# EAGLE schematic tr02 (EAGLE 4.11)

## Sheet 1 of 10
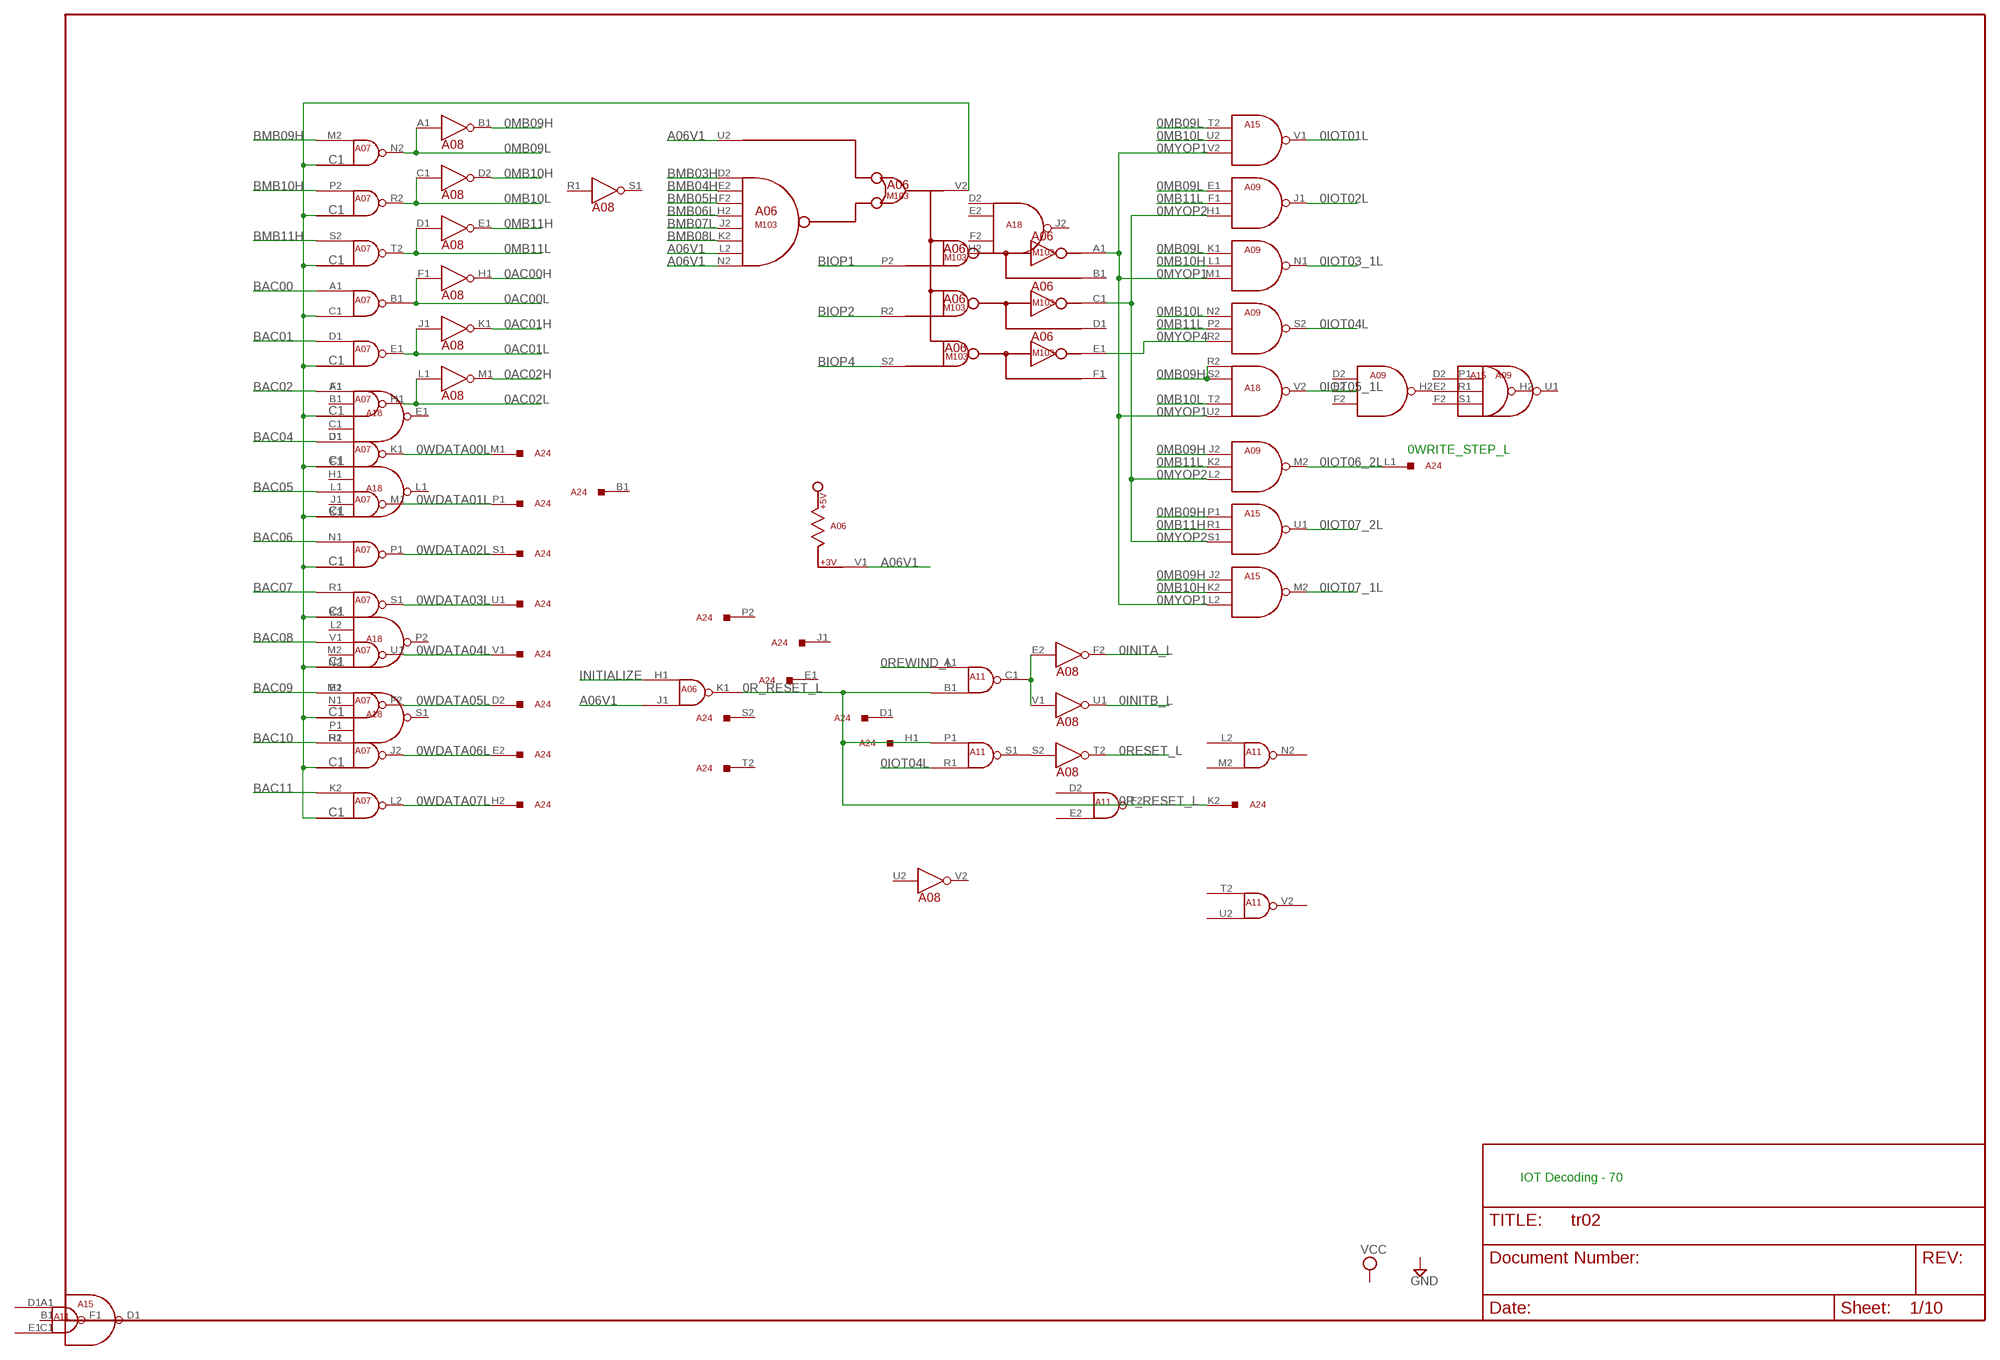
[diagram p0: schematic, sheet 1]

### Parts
A06  M103  [H807]
A07  M101  [H807]
A08  M111  [H807]
A09  M115  [H807]
A11  M113  [H807]
A15  M115  [H807]
A18  M117  [H807]
A24  G784  M916  [H807]

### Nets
0AC00H: A08.H1(4:OUT) ; also sheet 3
0AC00L: A07.B1(OUT) A08.F1(4:IN) ; also sheet 3
0AC01H: A08.K1(6:OUT) ; also sheet 3
0AC01L: A07.E1(OUT) A08.J1(6:IN) ; also sheet 3
0AC02H: A08.M1(8:OUT) ; also sheet 3
0AC02L: A07.H1(OUT) A08.L1(8:IN) ; also sheet 3
0INITA_L: A08.F2(5:OUT) ; also sheet 3
0INITB_L: A08.U1(14:OUT) ; also sheet 3
0IOT01L: A15.V1(OUT) ; also sheet 6
0IOT02L: A09.J1(OUT) ; also sheet 5
0IOT03_1L: A09.N1(OUT) ; also sheet 6
0IOT04L: A09.S2(OUT) A11.R1(IN2) ; also sheet 3
0IOT05_1L: A18.V2(OUT) ; also sheet 6
0IOT06_2L: A09.M2(OUT) A24.L1
0IOT07_1L: A15.M2(OUT) ; also sheet 6
0IOT07_2L: A15.U1(OUT) ; also sheet 5
0MB09H: A08.B1(1:OUT) A09.J2(IN1) A15.J2(IN1) A15.P1(IN1) A18.R2(IN1) A18.S2(IN2)
0MB09L: A07.N2(OUT) A08.A1(1:IN) A09.E1(IN1) A09.K1(IN1) A15.T2(IN1)
0MB10H: A08.D2(2:OUT) A09.L1(IN2) A15.K2(IN2)
0MB10L: A07.R2(OUT) A08.C1(2:IN) A09.N2(IN1) A15.U2(IN2) A18.T2(IN3)
0MB11H: A08.E1(3:OUT) A15.R1(IN2)
0MB11L: A07.T2(OUT) A08.D1(3:IN) A09.F1(IN2) A09.K2(IN2) A09.P2(IN2)
0MYOP1: A06.A1 A09.M1(IN3) A15.L2(IN3) A15.V2(IN3) A18.U2(IN4)
0MYOP2: A06.C1 A09.H1(IN3) A09.L2(IN3) A15.S1(IN3)
0MYOP4: A06.E1 A09.R2(IN3)
0R_RESET_L: A06.K1(OUT) A11.B1(IN2) A11.P1(IN1) A24.K2
0RESET_L: A08.T2(15:OUT) ; also sheet 5,6
0REWIND_L: A11.A1(IN1) ; also sheet 3
0WDATA00L: A07.K1(OUT) A24.M1
0WDATA01L: A07.M1(OUT) A24.P1
0WDATA02L: A07.P1(OUT) A24.S1
0WDATA03L: A07.S1(OUT) A24.U1
0WDATA04L: A07.U1(OUT) A24.V1
0WDATA05L: A07.F2(OUT) A24.D2
0WDATA06L: A07.J2(OUT) A24.E2
0WDATA07L: A07.L2(OUT) A24.H2
A06V1: A06.J1(IN2) A06.L2 A06.N2 A06.U2 A06.V1
BAC00: A07.A1(IN1) ; also sheet 2,10
BAC01: A07.D1(IN) ; also sheet 2,10
BAC02: A07.F1(IN) ; also sheet 2,10
BAC04: A07.J1(IN) ; also sheet 2,10
BAC05: A07.L1(IN) ; also sheet 2,10
BAC06: A07.N1(IN) ; also sheet 2,10
BAC07: A07.R1(IN) ; also sheet 2,10
BAC08: A07.V1(IN) ; also sheet 2,10
BAC09: A07.E2(IN) ; also sheet 2,10
BAC10: A07.H2(IN) ; also sheet 2,10
BAC11: A07.K2(IN) ; also sheet 2,10
BIOP1: A06.P2 ; also sheet 2,10
BIOP2: A06.R2 ; also sheet 2,10
BIOP4: A06.S2 ; also sheet 2,10
BMB03H: A06.D2 ; also sheet 2,10
BMB04H: A06.E2 ; also sheet 2,10
BMB05H: A06.F2 ; also sheet 2,10
BMB06L: A06.H2 ; also sheet 2,10
BMB07L: A06.J2 ; also sheet 2,10
BMB08L: A06.K2 ; also sheet 10
BMB09H: A07.M2(IN) ; also sheet 2,10
BMB10H: A07.P2(IN) ; also sheet 2,10
BMB11H: A07.S2(IN) ; also sheet 2,10
INITIALIZE: A06.H1(IN1) ; also sheet 2,10
N$7: A06.V2 A07.C1(IN2)
N$8: A08.S2(15:IN) A11.S1(OUT)
N$9: A08.E2(5:IN) A08.V1(14:IN) A11.C1(OUT)
Unconnected: A06.B1 A06.D1 A06.F1 A06.L1(IN1) A06.M1(IN2) A06.N1(OUT) A07.U2(IN) A07.V2(OUT) A11.V1 A18.U1 A18.V1 A24.A2 A24.B2 A24.M2 A24.V2

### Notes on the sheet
- 0WRITE_STEP_L
- IOT Decoding - 70

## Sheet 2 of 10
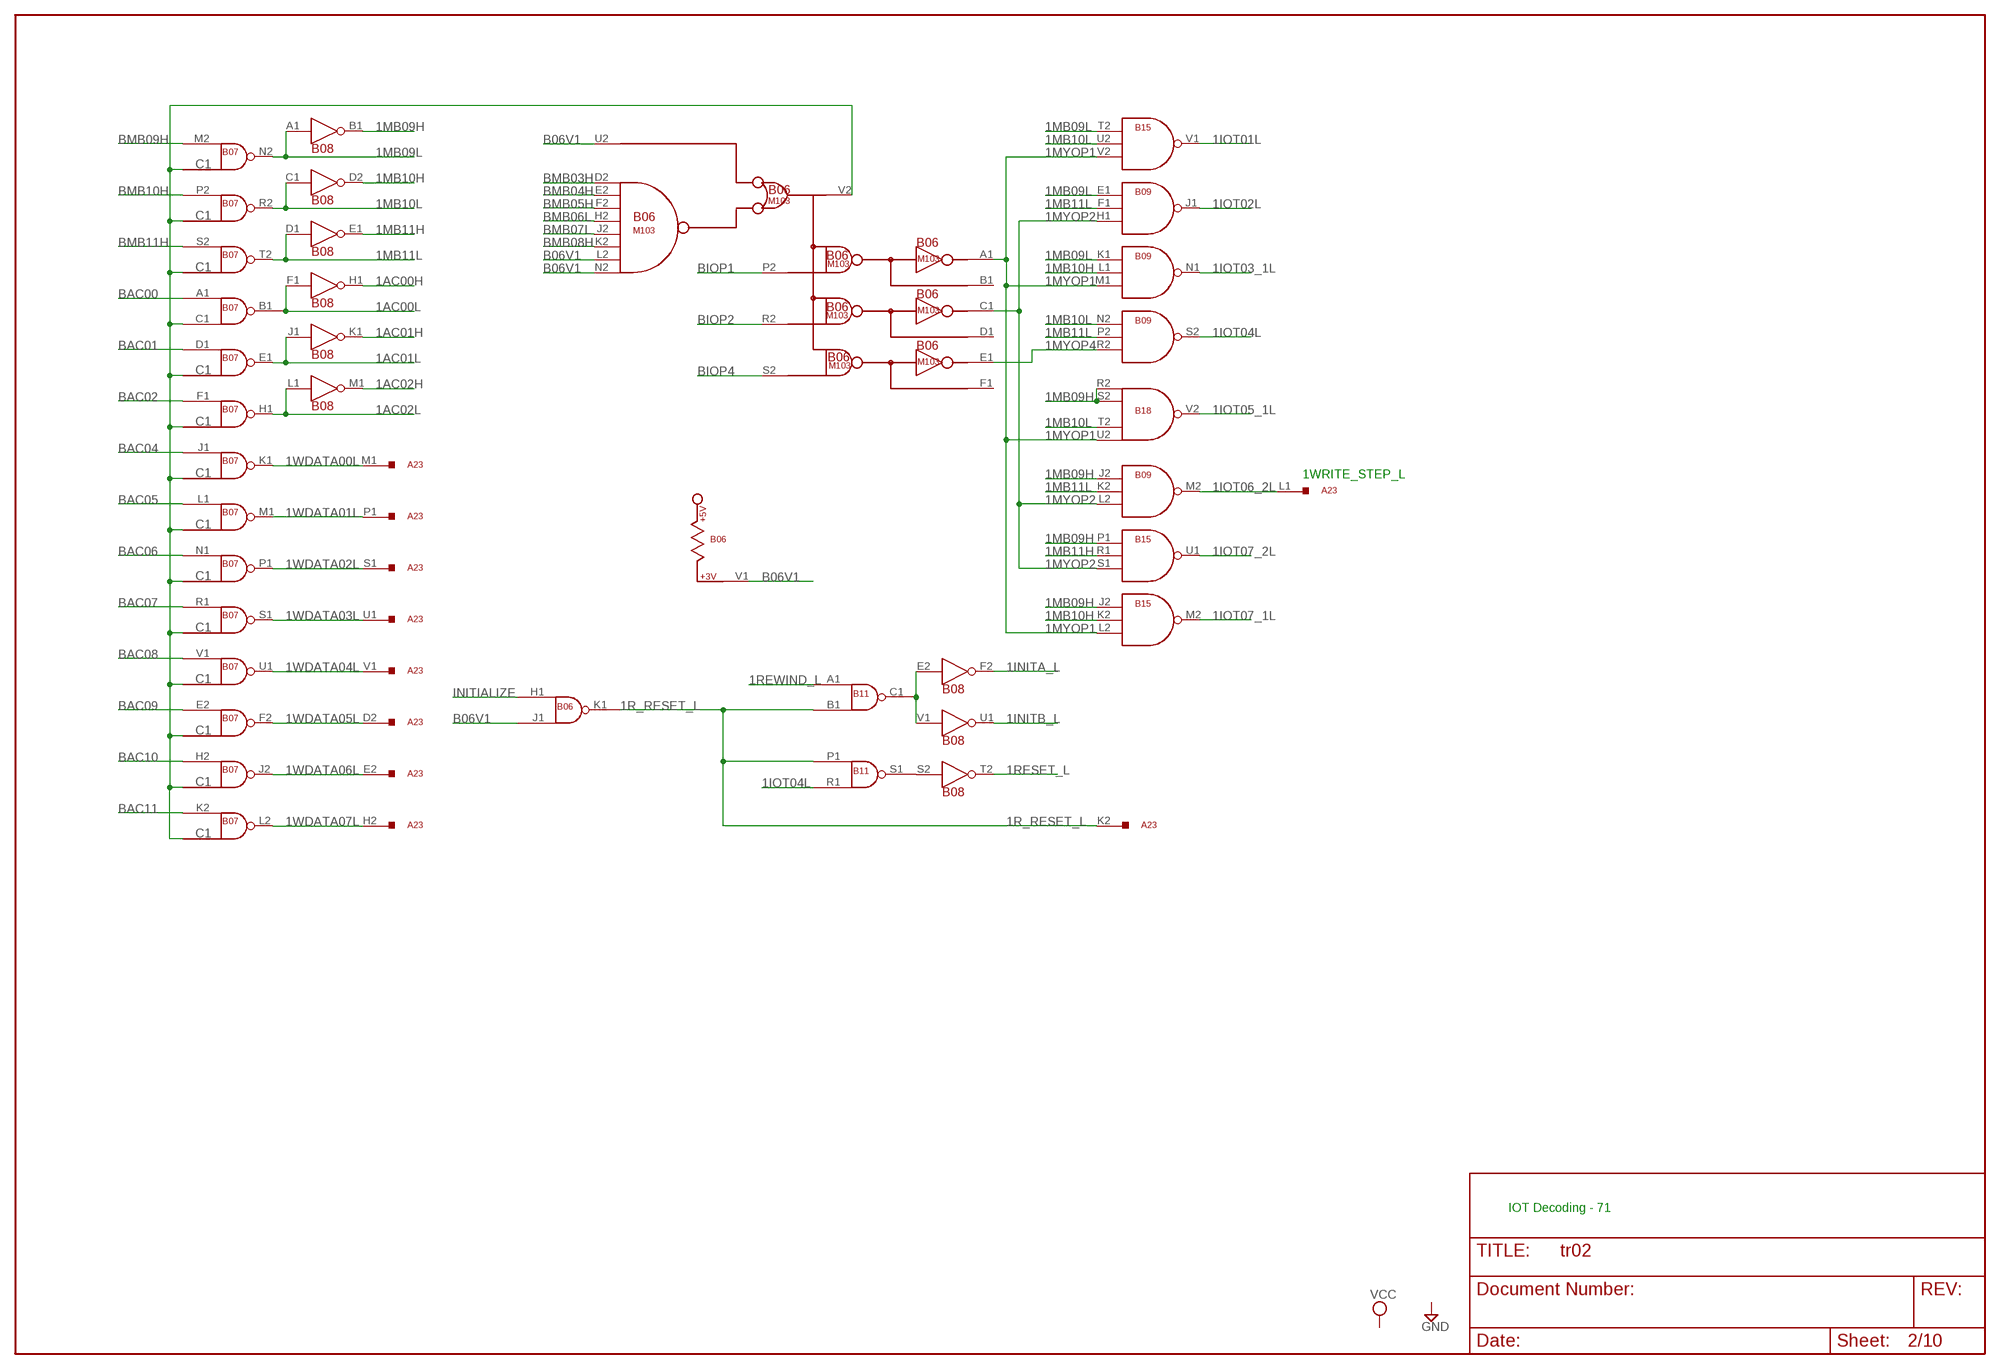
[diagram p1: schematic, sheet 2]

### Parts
A23  G784  M916  [H807]
B06  M103  [H807]
B07  M101  [H807]
B08  M111  [H807]
B09  M115  [H807]
B11  M113  [H807]
B15  M115  [H807]
B18  M117  [H807]

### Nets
1AC00H: B08.H1(4:OUT)
1AC00L: B07.B1(OUT) B08.F1(4:IN)
1AC01H: B08.K1(6:OUT)
1AC01L: B07.E1(OUT) B08.J1(6:IN)
1AC02H: B08.M1(8:OUT)
1AC02L: B07.H1(OUT) B08.L1(8:IN)
1INITA_L: B08.F2(5:OUT)
1INITB_L: B08.U1(14:OUT)
1IOT01L: B15.V1(OUT)
1IOT02L: B09.J1(OUT)
1IOT03_1L: B09.N1(OUT)
1IOT04L: B09.S2(OUT) B11.R1(IN2)
1IOT05_1L: B18.V2(OUT)
1IOT06_2L: A23.L1 B09.M2(OUT)
1IOT07_1L: B15.M2(OUT)
1IOT07_2L: B15.U1(OUT)
1MB09H: B08.B1(1:OUT) B09.J2(IN1) B15.J2(IN1) B15.P1(IN1) B18.R2(IN1) B18.S2(IN2)
1MB09L: B07.N2(OUT) B08.A1(1:IN) B09.E1(IN1) B09.K1(IN1) B15.T2(IN1)
1MB10H: B08.D2(2:OUT) B09.L1(IN2) B15.K2(IN2)
1MB10L: B07.R2(OUT) B08.C1(2:IN) B09.N2(IN1) B15.U2(IN2) B18.T2(IN3)
1MB11H: B08.E1(3:OUT) B15.R1(IN2)
1MB11L: B07.T2(OUT) B08.D1(3:IN) B09.F1(IN2) B09.K2(IN2) B09.P2(IN2)
1MYOP1: B06.A1 B09.M1(IN3) B15.L2(IN3) B15.V2(IN3) B18.U2(IN4)
1MYOP2: B06.C1 B09.H1(IN3) B09.L2(IN3) B15.S1(IN3)
1MYOP4: B06.E1 B09.R2(IN3)
1R_RESET_L: A23.K2 B06.K1(OUT) B11.B1(IN2) B11.P1(IN1)
1RESET_L: B08.T2(15:OUT)
1REWIND_L: B11.A1(IN1)
1WDATA00L: A23.M1 B07.K1(OUT)
1WDATA01L: A23.P1 B07.M1(OUT)
1WDATA02L: A23.S1 B07.P1(OUT)
1WDATA03L: A23.U1 B07.S1(OUT)
1WDATA04L: A23.V1 B07.U1(OUT)
1WDATA05L: A23.D2 B07.F2(OUT)
1WDATA06L: A23.E2 B07.J2(OUT)
1WDATA07L: A23.H2 B07.L2(OUT)
B06V1: B06.J1(IN2) B06.L2 B06.N2 B06.U2 B06.V1
BAC00: B07.A1(IN1) ; also sheet 1,10
BAC01: B07.D1(IN) ; also sheet 1,10
BAC02: B07.F1(IN) ; also sheet 1,10
BAC04: B07.J1(IN) ; also sheet 1,10
BAC05: B07.L1(IN) ; also sheet 1,10
BAC06: B07.N1(IN) ; also sheet 1,10
BAC07: B07.R1(IN) ; also sheet 1,10
BAC08: B07.V1(IN) ; also sheet 1,10
BAC09: B07.E2(IN) ; also sheet 1,10
BAC10: B07.H2(IN) ; also sheet 1,10
BAC11: B07.K2(IN) ; also sheet 1,10
BIOP1: B06.P2 ; also sheet 1,10
BIOP2: B06.R2 ; also sheet 1,10
BIOP4: B06.S2 ; also sheet 1,10
BMB03H: B06.D2 ; also sheet 1,10
BMB04H: B06.E2 ; also sheet 1,10
BMB05H: B06.F2 ; also sheet 1,10
BMB06L: B06.H2 ; also sheet 1,10
BMB07L: B06.J2 ; also sheet 1,10
BMB08H: B06.K2 ; also sheet 10
BMB09H: B07.M2(IN) ; also sheet 1,10
BMB10H: B07.P2(IN) ; also sheet 1,10
BMB11H: B07.S2(IN) ; also sheet 1,10
INITIALIZE: B06.H1(IN1) ; also sheet 1,10
N$1: B06.V2 B07.C1(IN2)
N$2: B08.S2(15:IN) B11.S1(OUT)
N$3: B08.E2(5:IN) B08.V1(14:IN) B11.C1(OUT)
Unconnected: A23.A2 A23.B1 A23.B2 A23.D1 A23.E1 A23.H1 A23.J1 A23.M2 A23.P2 A23.S2 A23.T2 A23.V2 B06.B1 B06.D1 B06.F1 B06.L1(IN1) B06.M1(IN2) B06.N1(OUT) B07.U2(IN) B07.V2(OUT) B08.H2(7:IN) B08.J2(7:OUT) B08.K2(9:IN) B08.L2(9:OUT) B08.M2(11:IN) B08.N1(10:IN) B08.N2(11:OUT) B08.P1(10:OUT) B08.P2(13:IN) B08.R1(12:IN) B08.R2(13:OUT) B08.S1(12:OUT) B08.U2(16:IN) B08.V2(16:OUT) B09.A1(IN1) B09.B1(IN2) B09.C1(IN3) B09.D1(OUT) B09.D2(IN1) B09.E2(IN2) B09.F2(IN3) B09.H2(OUT) B09.P1(IN1) B09.R1(IN2) B09.S1(IN3) B09.T2(IN1) B09.U1(OUT) B09.U2(IN2) B09.V1(OUT) B09.V2(IN3) B11.D1(IN1) B11.D2(IN1) B11.E1(IN2) B11.E2(IN2) B11.F1(OUT) B11.F2(OUT) B11.H1(IN1) B11.H2(IN1) B11.J1(IN2) B11.J2(IN2) B11.K1(OUT) B11.K2(OUT) B11.L1(IN1) B11.L2(IN1) B11.M1(IN2) B11.M2(IN2) B11.N1(OUT) B11.N2(OUT) B11.P2(IN1) B11.R2(IN2) B11.S2(OUT) B11.T2(IN1) B11.U1 B11.U2(IN2) B11.V1 B11.V2(OUT) B15.A1(IN1) B15.B1(IN2) B15.C1(IN3) B15.D1(OUT) B15.D2(IN1) B15.E1(IN1) B15.E2(IN2) B15.F1(IN2) B15.F2(IN3) B15.H1(IN3) B15.H2(OUT) B15.J1(OUT) B15.K1(IN1) B15.L1(IN2) B15.M1(IN3) B15.N1(OUT) B15.N2(IN1) B15.P2(IN2) B15.R2(IN3) B15.S2(OUT) B18.A1(IN1) B18.B1(IN2) B18.C1(IN3) B18.D1(IN4) B18.D2(IN1) B18.E1(OUT) B18.E2(IN2) B18.F1(IN1) B18.F2(IN3) B18.H1(IN2) B18.H2(IN4) B18.J1(IN3) B18.J2(OUT) B18.K1(IN4) B18.K2(IN1) B18.L1(OUT) B18.L2(IN2) B18.M1(IN1) B18.M2(IN3) B18.N1(IN2) B18.N2(IN4) B18.P1(IN3) B18.P2(OUT) B18.R1(IN4) B18.S1(OUT) B18.U1 B18.V1

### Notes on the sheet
- 1WRITE_STEP_L
- IOT Decoding - 71

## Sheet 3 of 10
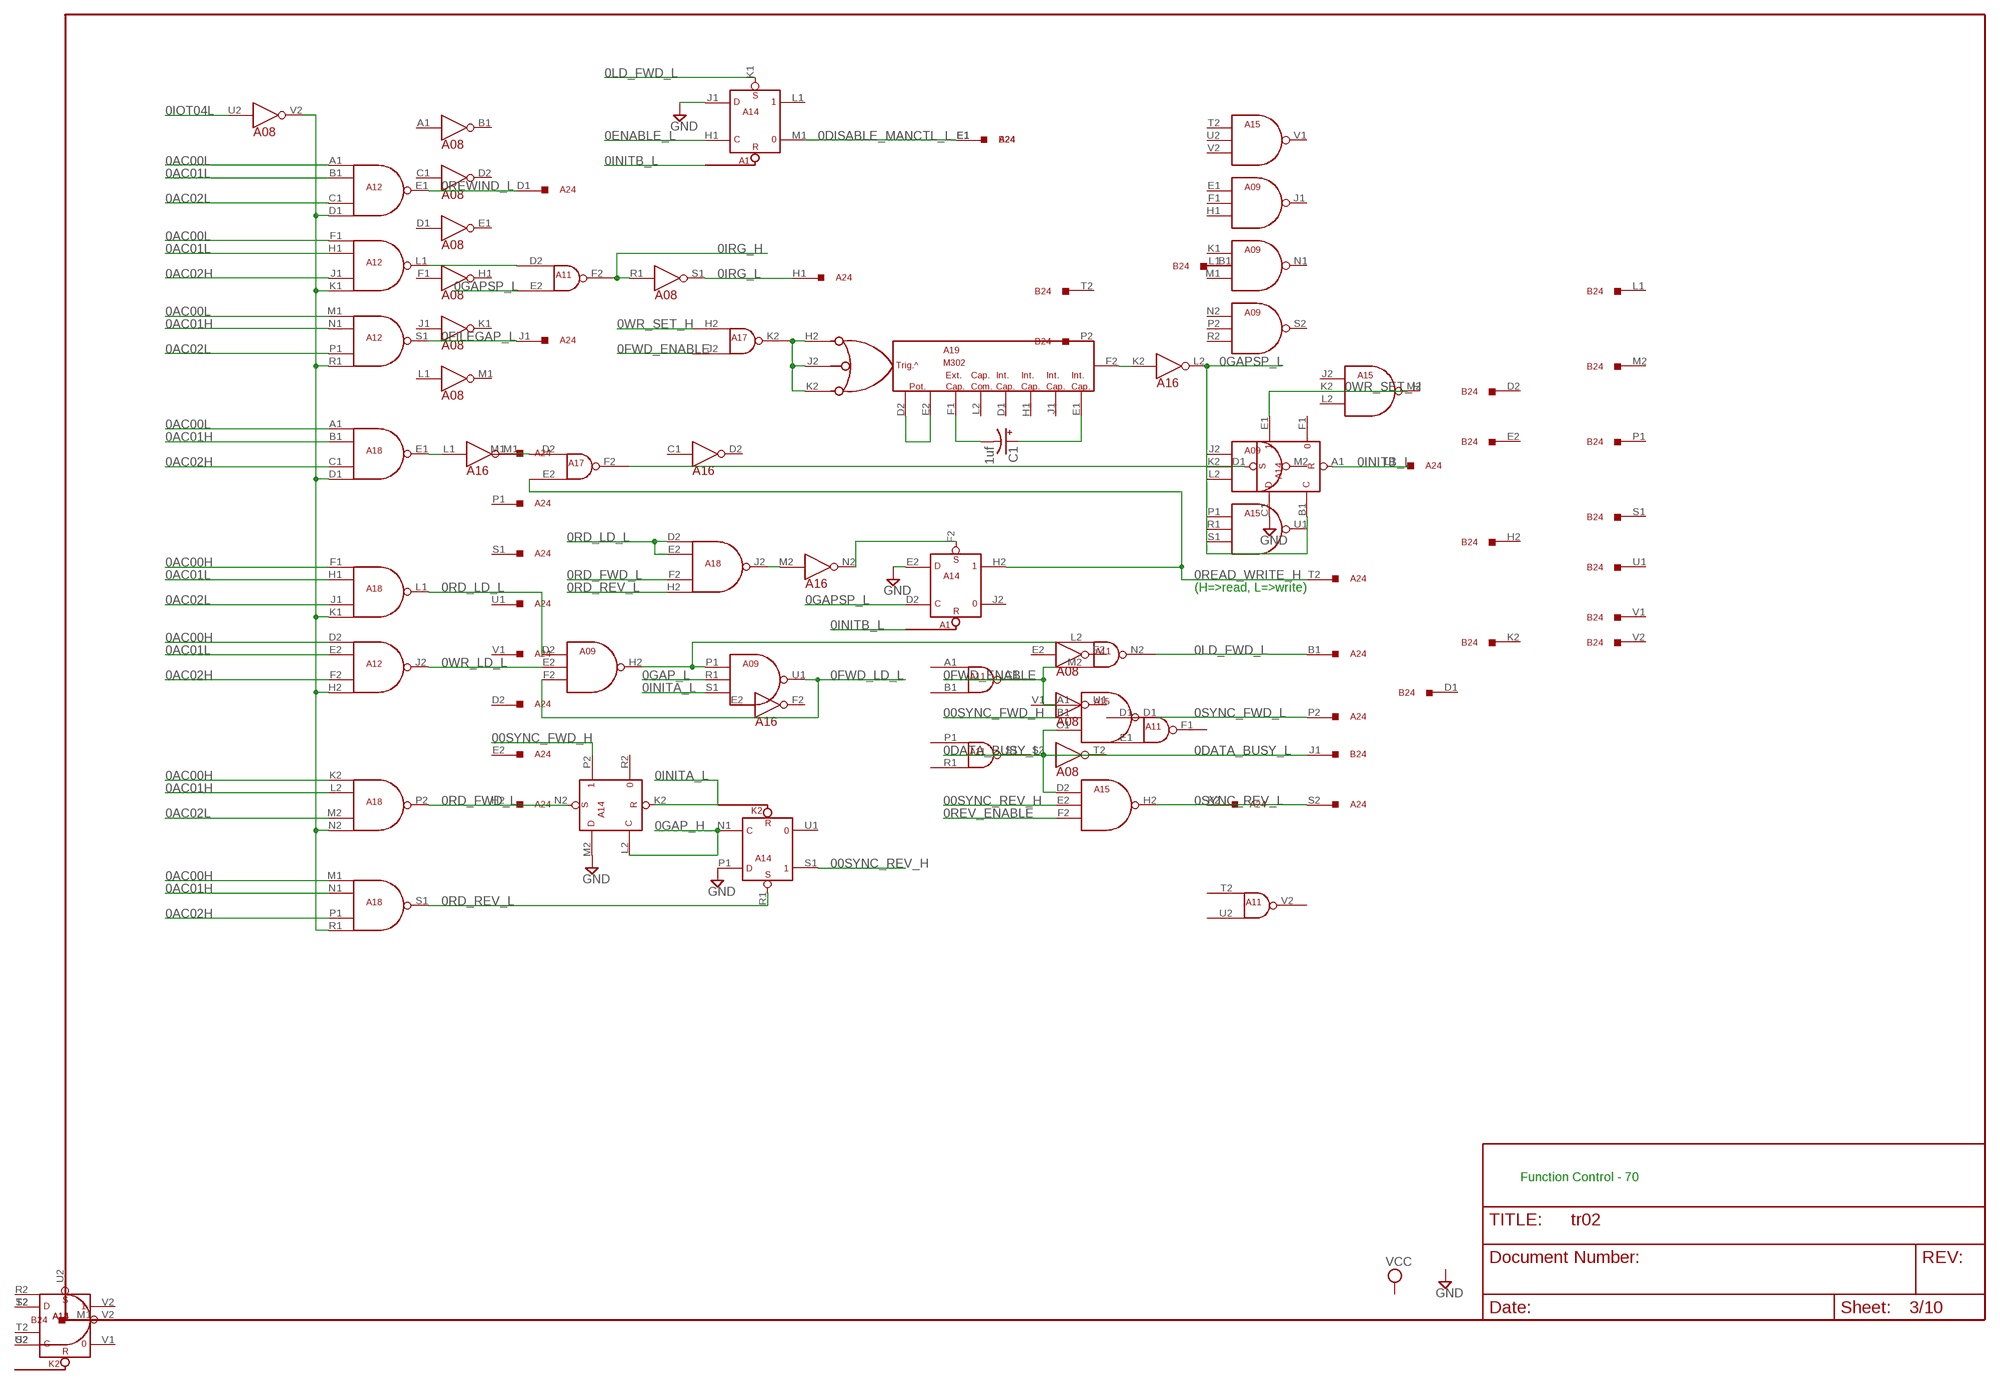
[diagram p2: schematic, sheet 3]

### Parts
A12  M117  [H807]
A14  M206X  [H807]
A16  M111  [H807]
A17  M113  [H807]
A19  M302  [H807]
B24  G784  M916  [H807]
C1  1uf  CPOL-USE22-6AXIAL  [E22-6]

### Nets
0AC00H: A12.D2(IN1) A18.F1(IN1) A18.K2(IN1) A18.M1(IN1) ; also sheet 1
0AC00L: A12.A1(IN1) A12.F1(IN1) A12.M1(IN1) A18.A1(IN1) ; also sheet 1
0AC01H: A12.N1(IN2) A18.B1(IN2) A18.L2(IN2) A18.N1(IN2) ; also sheet 1
0AC01L: A12.B1(IN2) A12.E2(IN2) A12.H1(IN2) A18.H1(IN2) ; also sheet 1
0AC02H: A12.F2(IN3) A12.J1(IN3) A18.C1(IN3) A18.P1(IN3) ; also sheet 1
0AC02L: A12.C1(IN3) A12.P1(IN3) A18.J1(IN3) A18.M2(IN3) ; also sheet 1
0DATA_BUSY_L: A15.C1(IN3) A15.D2(IN1) B24.J1
0DISABLE_MANCTL_L: A14.M1 A24.E1 ; also sheet 4
0ENABLE_L: A14.H1(A1C:C) ; also sheet 7
0FILEGAP_L: A12.S1(OUT) A24.J1
0FWD_ENABLE: A11.M2(IN2) A15.A1(IN1) A17.J2(IN2) ; also sheet 4
0FWD_LD_L: A09.F2(IN3) A09.U1(OUT) ; also sheet 4
0GAP_H: A14.L2(K2:C) A14.N1(K2B:C) ; also sheet 4,6
0GAP_L: A09.R1(IN2) ; also sheet 4
0GAPSP_L: A11.E2(IN2) A14.B1(A1:C) A14.D2(A1B:C) A16.L2(9:OUT)
0INITA_L: A09.S1(IN3) A14.K2(K2:R) ; also sheet 1
0INITB_L: A14.A1(A1:R) ; also sheet 1
0IOT04L: A08.U2(16:IN) ; also sheet 1
0IRG_H: A08.R1(12:IN) A11.F2(OUT)
0IRG_L: A08.S1(12:OUT) A24.H1 ; also sheet 4
0LD_FWD_L: A11.N2(OUT) A14.K1(A1C:S) A24.B1
0RD_FWD_L: A14.N2(K2:S) A18.F2(IN3) A18.P2(OUT)
0RD_LD_L: A09.D2(IN1) A18.D2(IN1) A18.E2(IN2) A18.L1(OUT)
0RD_REV_L: A14.R1(K2B:S) A18.H2(IN4) A18.S1(OUT)
0READ_WRITE_H: A14.H2 A17.E2(IN2) A24.T2 ; also sheet 5,6
0REV_ENABLE: A15.F2(IN3) ; also sheet 4
0REWIND_L: A12.E1(OUT) A24.D1 ; also sheet 1
00SYNC_FWD_H: A14.P2 A15.B1(IN2)
0SYNC_FWD_L: A15.D1(OUT) A24.P2 ; also sheet 4
00SYNC_REV_H: A14.S1 A15.E2(IN2)
0SYNC_REV_L: A15.H2(OUT) A24.S2 ; also sheet 4
0WR_LD_L: A09.E2(IN2) A12.J2(OUT)
0WR_SET_H: A14.E1 A17.H2(IN1)
GND [supply]: A14.C1(A1:D) A14.E2(A1B:D) A14.J1(A1C:D) A14.M2(K2:D) A14.P1(K2B:D) ; also sheet 5,6,7,10
N$4: A16.M1(8:OUT) A17.D2(IN1)
N$5: A16.L1(8:IN) A18.E1(OUT)
N$6: A17.K2(OUT) A19.H2 A19.J2 A19.K2
N$10: A19.F1 C1.-
N$11: A11.D2(IN1) A12.L1(OUT)
N$12: A08.V2(16:OUT) A12.D1(IN4) A12.H2(IN4) A12.K1(IN4) A12.R1(IN4) A18.D1(IN4) A18.K1(IN4) A18.N2(IN4) A18.R1(IN4)
N$13: A19.E1 C1.+
N$14: A19.D2 A19.E2
N$15: A16.K2(9:IN) A19.F2
N$16: A14.D1(A1:S) A17.F2(OUT)
N$17: A14.F2(A1B:S) A16.N2(11:OUT)
N$18: A09.H2(OUT) A09.P1(IN1) A11.L2(IN1)
N$19: A16.M2(11:IN) A18.J2(OUT)
Unconnected: A12.U1 A12.V1 A16.P2(13:IN) A16.R2(13:OUT) A16.S2(15:IN) A16.T2(15:OUT) A16.U1(14:OUT) A16.U2(16:IN) A16.V1(14:IN) A16.V2(16:OUT) A17.U1 A17.V1 B24.A2 B24.B2 B24.S2

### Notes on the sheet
- (H=>read, L=>write)
- Function Control - 70

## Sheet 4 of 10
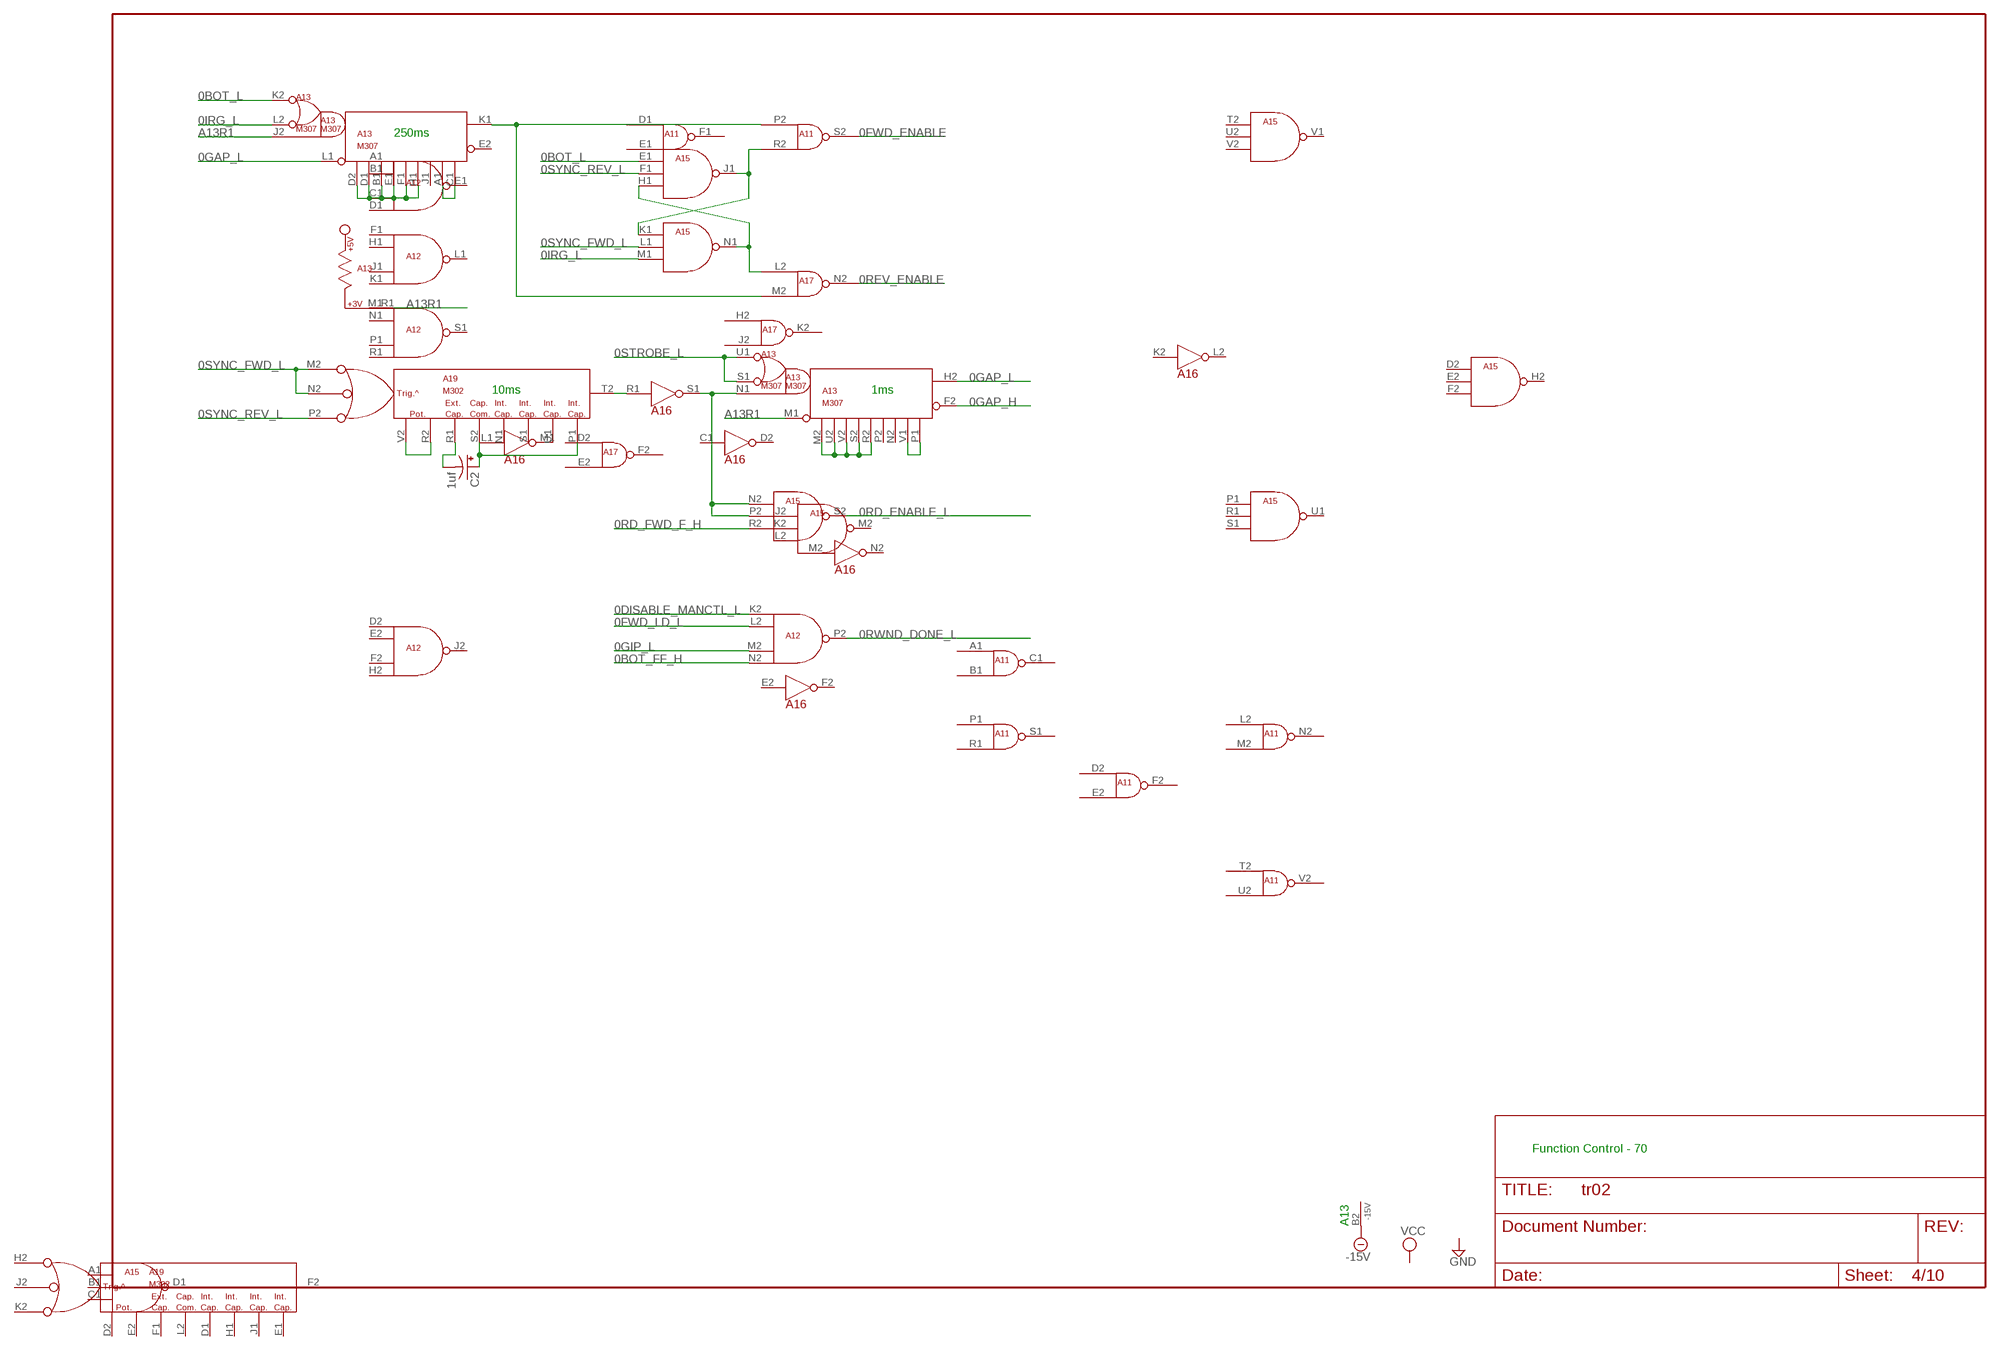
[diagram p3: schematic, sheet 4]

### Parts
A13  M307  [H807]
C2  1uf  CPOL-USE22-6AXIAL  [E22-6]

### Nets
0BOT_FF_H: A12.N2(IN4) ; also sheet 5
0BOT_L: A13.K2(U1) A15.E1(IN1) ; also sheet 5
0DISABLE_MANCTL_L: A12.K2(IN1) ; also sheet 3
0FWD_ENABLE: A11.S2(OUT) ; also sheet 3
0FWD_LD_L: A12.L2(IN2) ; also sheet 3
0GAP_H: A13.F2 ; also sheet 3,6
0GAP_L: A13.H2 A13.L1(M1) ; also sheet 3
0GIP_L: A12.M2(IN3) ; also sheet 5
0IRG_L: A13.L2(S1) A15.M1(IN3) ; also sheet 3
0RD_ENABLE_L: A15.S2(OUT) ; also sheet 6
0RD_FWD_F_H: A15.R2(IN3)
0REV_ENABLE: A17.N2(OUT) ; also sheet 3
0RWND_DONE_L: A12.P2(OUT) ; also sheet 6
0STROBE_L: A13.S1 A13.U1 ; also sheet 6
0SYNC_FWD_L: A15.L1(IN2) A19.M2(H2) A19.N2(J2) ; also sheet 3
0SYNC_REV_L: A15.F1(IN2) A19.P2(K2) ; also sheet 3
-15V: A13.B2(-15V)
A13R1: A13.J2(N1) A13.M1 A13.R1
N$20: A13.B1(V2) A13.D1(U2) A13.D2(M2) A13.E1(S2) A13.F1(R2) A13.H1(P2)
N$21: A15.H1(IN3) A15.N1(OUT) A17.L2(IN1)
N$22: A13.A1(V1) A13.C1(P1)
N$23: A11.P2(IN1) A13.K1(H2) A17.M2(IN2)
N$24: A11.R2(IN2) A15.J1(OUT) A15.K1(IN1)
N$25: A19.R2(E2) A19.V2(D2)
N$26: A19.R1(F1) C2.-
N$27: A19.P1(E1) A19.S2(L2) C2.+
N$28: A16.R1(12:IN) A19.T2(F2)
N$29: A13.N1 A15.N2(IN1) A15.P2(IN2) A16.S1(12:OUT)
N$30: A13.M2 A13.R2 A13.S2 A13.U2 A13.V2
N$31: A13.P1 A13.V1
Unconnected: A13.E2(F2) A13.J1(N2) A13.N2 A13.P2 A19.D1 A19.H1 A19.J1 A19.L2 A19.N1(D1) A19.S1(H1) A19.U1(J1)

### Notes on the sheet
- 250ms
- 10ms | 1ms
- Function Control - 70
- A13

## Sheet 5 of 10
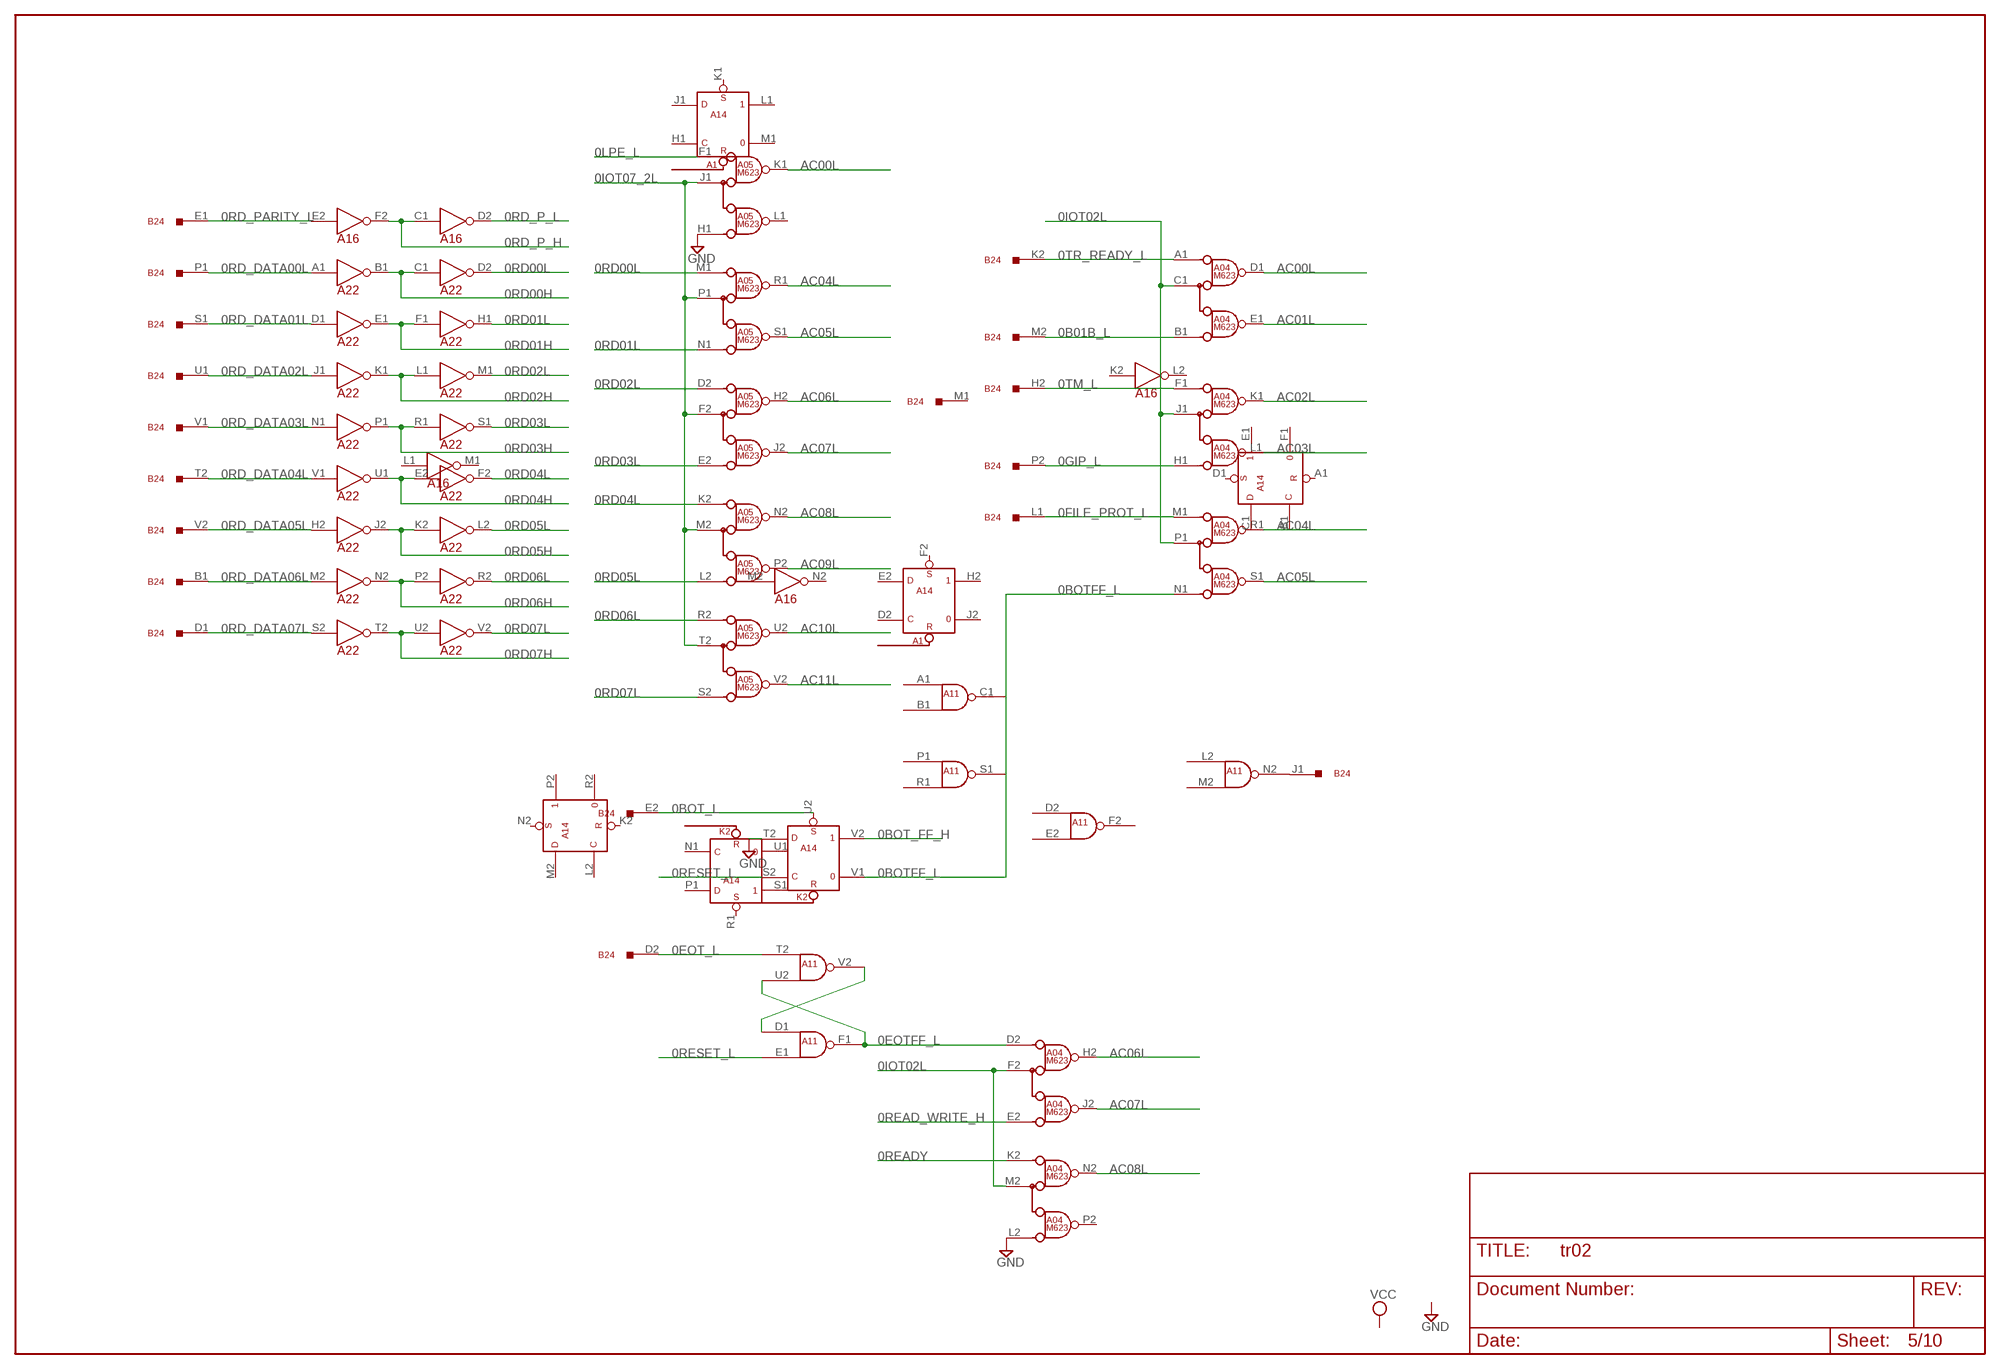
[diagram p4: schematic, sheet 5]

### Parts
A04  M623  [H807]
A05  M623  [H807]
A22  M111  [H807]

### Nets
0B01B_L: A04.B1(B) B24.M2
0BOT_FF_H: A14.V2 ; also sheet 4
0BOT_L: A14.U2(K2C:S) B24.E2 ; also sheet 4
0BOTFF_L: A04.N1(B) A14.V1
0EOT_L: A11.T2(IN1) B24.D2
0EOTFF_L: A04.D2(A) A11.F1(OUT) A11.U2(IN2)
0FILE_PROT_L: A04.M1(A) B24.L1
0GIP_L: A04.H1(B) B24.P2 ; also sheet 4
0IOT02L: A04.C1(C) A04.F2(C) A04.J1(C) A04.M2(C) A04.P1(C) ; also sheet 1
0IOT07_2L: A05.F2(C) A05.J1(C) A05.M2(C) A05.P1(C) A05.T2(C) ; also sheet 1
0LPE_L: A05.F1(A) ; also sheet 7
0RD00H: A22.B1(1:OUT) A22.C1(2:IN) ; also sheet 7
0RD00L: A05.M1(A) A22.D2(2:OUT) ; also sheet 7
0RD01H: A22.E1(3:OUT) A22.F1(4:IN) ; also sheet 7
0RD01L: A05.N1(B) A22.H1(4:OUT) ; also sheet 7
0RD02H: A22.K1(6:OUT) A22.L1(8:IN) ; also sheet 7
0RD02L: A05.D2(A) A22.M1(8:OUT) ; also sheet 7
0RD03H: A22.P1(10:OUT) A22.R1(12:IN) ; also sheet 7
0RD03L: A05.E2(B) A22.S1(12:OUT) ; also sheet 7
0RD04H: A22.E2(5:IN) A22.U1(14:OUT) ; also sheet 7
0RD04L: A05.K2(A) A22.F2(5:OUT) ; also sheet 7
0RD05H: A22.J2(7:OUT) A22.K2(9:IN) ; also sheet 7
0RD05L: A05.L2(B) A22.L2(9:OUT) ; also sheet 7
0RD06H: A22.N2(11:OUT) A22.P2(13:IN) ; also sheet 7
0RD06L: A05.R2(A) A22.R2(13:OUT) ; also sheet 7
0RD07H: A22.T2(15:OUT) A22.U2(16:IN) ; also sheet 7
0RD07L: A05.S2(B) A22.V2(16:OUT) ; also sheet 7
0RD_DATA00L: A22.A1(1:IN) B24.P1
0RD_DATA01L: A22.D1(3:IN) B24.S1
0RD_DATA02L: A22.J1(6:IN) B24.U1
0RD_DATA03L: A22.N1(10:IN) B24.V1
0RD_DATA04L: A22.V1(14:IN) B24.T2
0RD_DATA05L: A22.H2(7:IN) B24.V2
0RD_DATA06L: A22.M2(11:IN) B24.B1
0RD_DATA07L: A22.S2(15:IN) B24.D1
0RD_P_H: A16.C1(2:IN) A16.F2(5:OUT) ; also sheet 7
0RD_P_L: A16.D2(2:OUT)
0RD_PARITY_L: A16.E2(5:IN) B24.E1
0READ_WRITE_H: A04.E2(B) ; also sheet 3,6
0READY: A04.K2(A)
0RESET_L: A11.E1(IN2) A14.S2(K2C:C) ; also sheet 1,6
0TM_L: A04.F1(A) B24.H2
0TR_READY_L: A04.A1(A) B24.K2 ; also sheet 6
AC00L: A04.D1(D) A05.K1(D) ; also sheet 10
AC01L: A04.E1(E) ; also sheet 10
AC02L: A04.K1(D) ; also sheet 10
AC03L: A04.L1(E) ; also sheet 10
AC04L: A04.R1(D) A05.R1(D) ; also sheet 10
AC05L: A04.S1(E) A05.S1(E) ; also sheet 10
AC06L: A04.H2(D) A05.H2(D) ; also sheet 10
AC07L: A04.J2(E) A05.J2(E) ; also sheet 10
AC08L: A04.N2(D) A05.N2(D) ; also sheet 10
AC09L: A05.P2(E) ; also sheet 10
AC10L: A05.U2(D) ; also sheet 10
AC11L: A05.V2(E) ; also sheet 10
GND [supply]: A04.L2(B) A05.H1(B) A14.T2(K2C:D) ; also sheet 3,6,7,10
N$33: A11.D1(IN1) A11.V2(OUT)
Unconnected: A14.F1 A14.J2 A14.L1 A14.R2 A14.U1

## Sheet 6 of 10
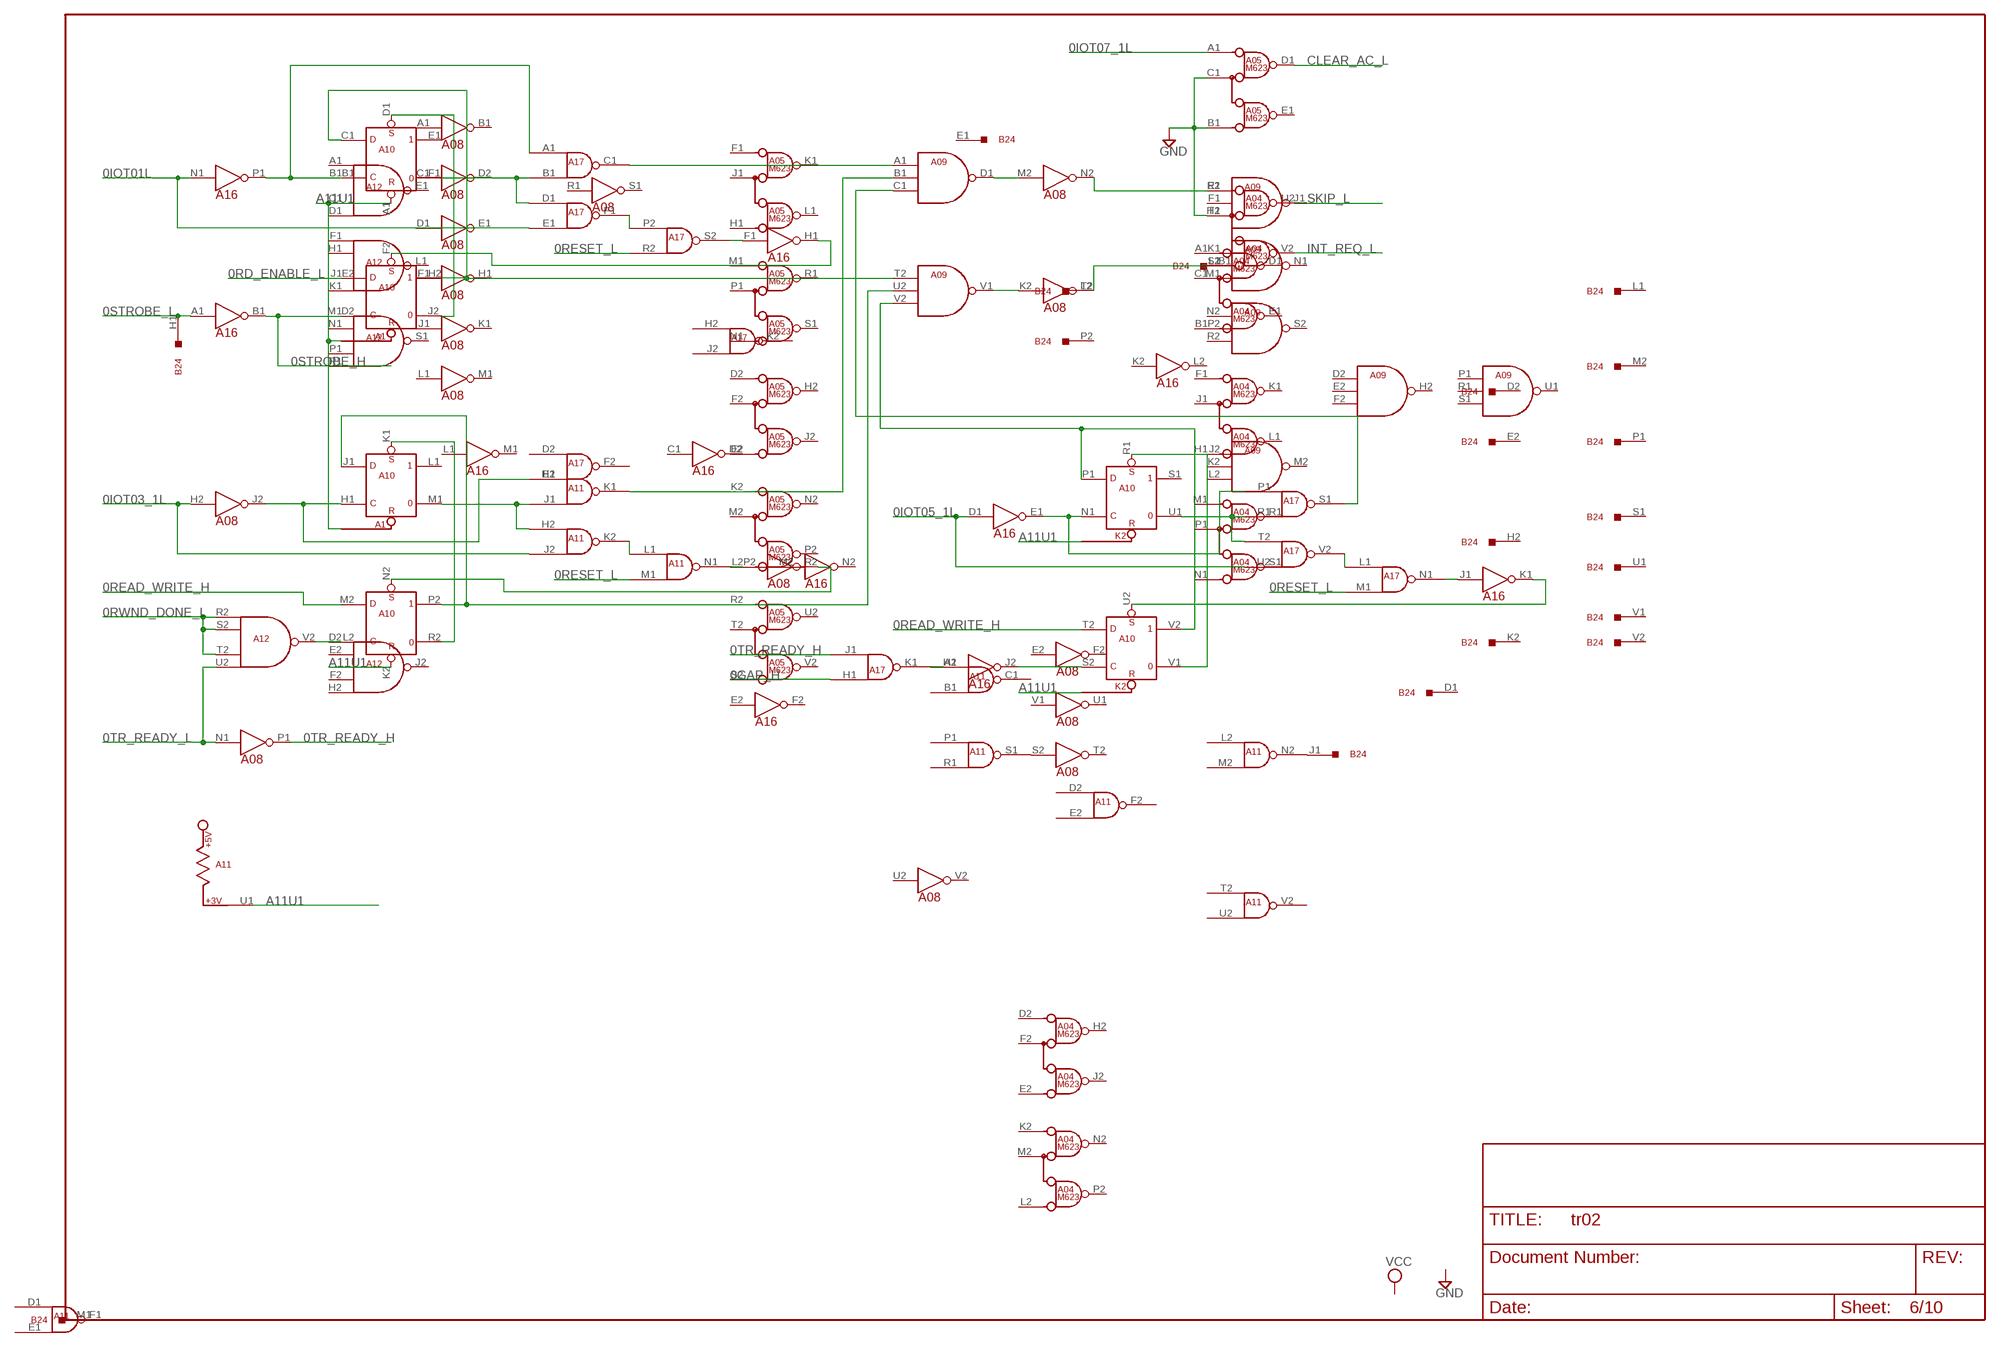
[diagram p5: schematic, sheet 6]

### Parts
A10  M206X  [H807]

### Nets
0GAP_H: A17.H1(IN1) ; also sheet 3,4
0IOT01L: A16.N1(10:IN) A17.E1(IN2) ; also sheet 1
0IOT03_1L: A08.H2(7:IN) A11.J2(IN2) ; also sheet 1
0IOT05_1L: A16.D1(3:IN) A17.U2(IN2) ; also sheet 1
0IOT07_1L: A05.A1(A) ; also sheet 1
0RD_ENABLE_L: A10.E2(A1B:D) ; also sheet 4
0READ_WRITE_H: A10.M2(K2:D) A10.T2(K2C:D) ; also sheet 3,5
0RESET_L: A11.M1(IN2) A17.M1(IN2) A17.R2(IN2) ; also sheet 1,5
0RWND_DONE_L: A12.R2(IN1) A12.S2(IN2) A12.T2(IN3) ; also sheet 4
0STROBE_H: A10.D2(A1B:C) A16.B1(1:OUT)
0STROBE_L: A16.A1(1:IN) B24.H1 ; also sheet 4
0TR_READY_H: A08.P1(10:OUT) A17.J1(IN2)
0TR_READY_L: A08.N1(10:IN) A12.U2(IN4) ; also sheet 5
A11U1: A10.A1(A1:R) A10.K2(K2:R) A11.U1
CLEAR_AC_L: A05.D1(D) ; also sheet 10
GND [supply]: A04.T2(C) A05.B1(B) A05.C1(C) ; also sheet 3,5,7,10
INT_REQ_L: A04.V2(E) ; also sheet 10
N$32: A10.B1(A1:C) A16.P1(10:OUT) A17.A1(IN1)
N$34: A16.F1(4:IN) A17.S2(OUT)
N$35: A08.J2(7:OUT) A10.H1(A1C:C) A11.H1(IN1)
N$36: A10.L2(K2:C) A12.V2(OUT)
N$37: A10.D1(A1:S) A10.J2
N$38: A09.T2(IN1) A10.C1(A1:D) A10.H2
N$39: A10.F2(A1B:S) A16.H1(4:OUT)
N$40: A10.F1 A17.B1(IN2) A17.D1(IN1)
N$41: A17.F1(OUT) A17.P2(IN1)
N$42: A09.A1(IN1) A17.C1(OUT)
N$43: A10.K1(A1C:S) A10.R2
N$44: A09.U2(IN2) A10.J1(A1C:D) A10.P2
N$45: A10.M1 A11.H2(IN1) A11.J1(IN2)
N$46: A16.H2(7:IN) A17.K1(OUT)
N$47: A09.B1(IN2) A11.K1(OUT)
N$48: A11.K2(OUT) A11.L1(IN1)
N$49: A08.P2(13:IN) A11.N1(OUT)
N$50: A08.R2(13:OUT) A10.N2(K2:S)
N$51: A08.K2(9:IN) A09.V1(OUT)
N$52: A08.M2(11:IN) A09.D1(OUT)
N$53: A10.S2(K2C:C) A16.J2(7:OUT)
N$54: A10.N1(K2B:C) A16.E1(3:OUT) A17.P1(IN1)
N$55: A04.R2(A) A08.N2(11:OUT)
N$56: A04.S2(B) A08.L2(9:OUT)
N$57: A09.V2(IN3) A10.P1(K2B:D) A10.V2
N$58: A10.R1(K2B:S) A10.V1
N$59: A10.U2(K2C:S) A16.K1(6:OUT)
N$60: A10.U1 A17.R1(IN2) A17.T2(IN1)
N$62: A17.L1(IN1) A17.V2(OUT)
N$63: A16.J1(6:IN) A17.N1(OUT)
N$65: A09.C1(IN3) A17.S1(OUT)
SKIP_L: A04.U2(D) ; also sheet 10
Unconnected: A04.P2(E) A05.E1(E) A05.L1(E) A10.E1 A10.L1 A10.S1

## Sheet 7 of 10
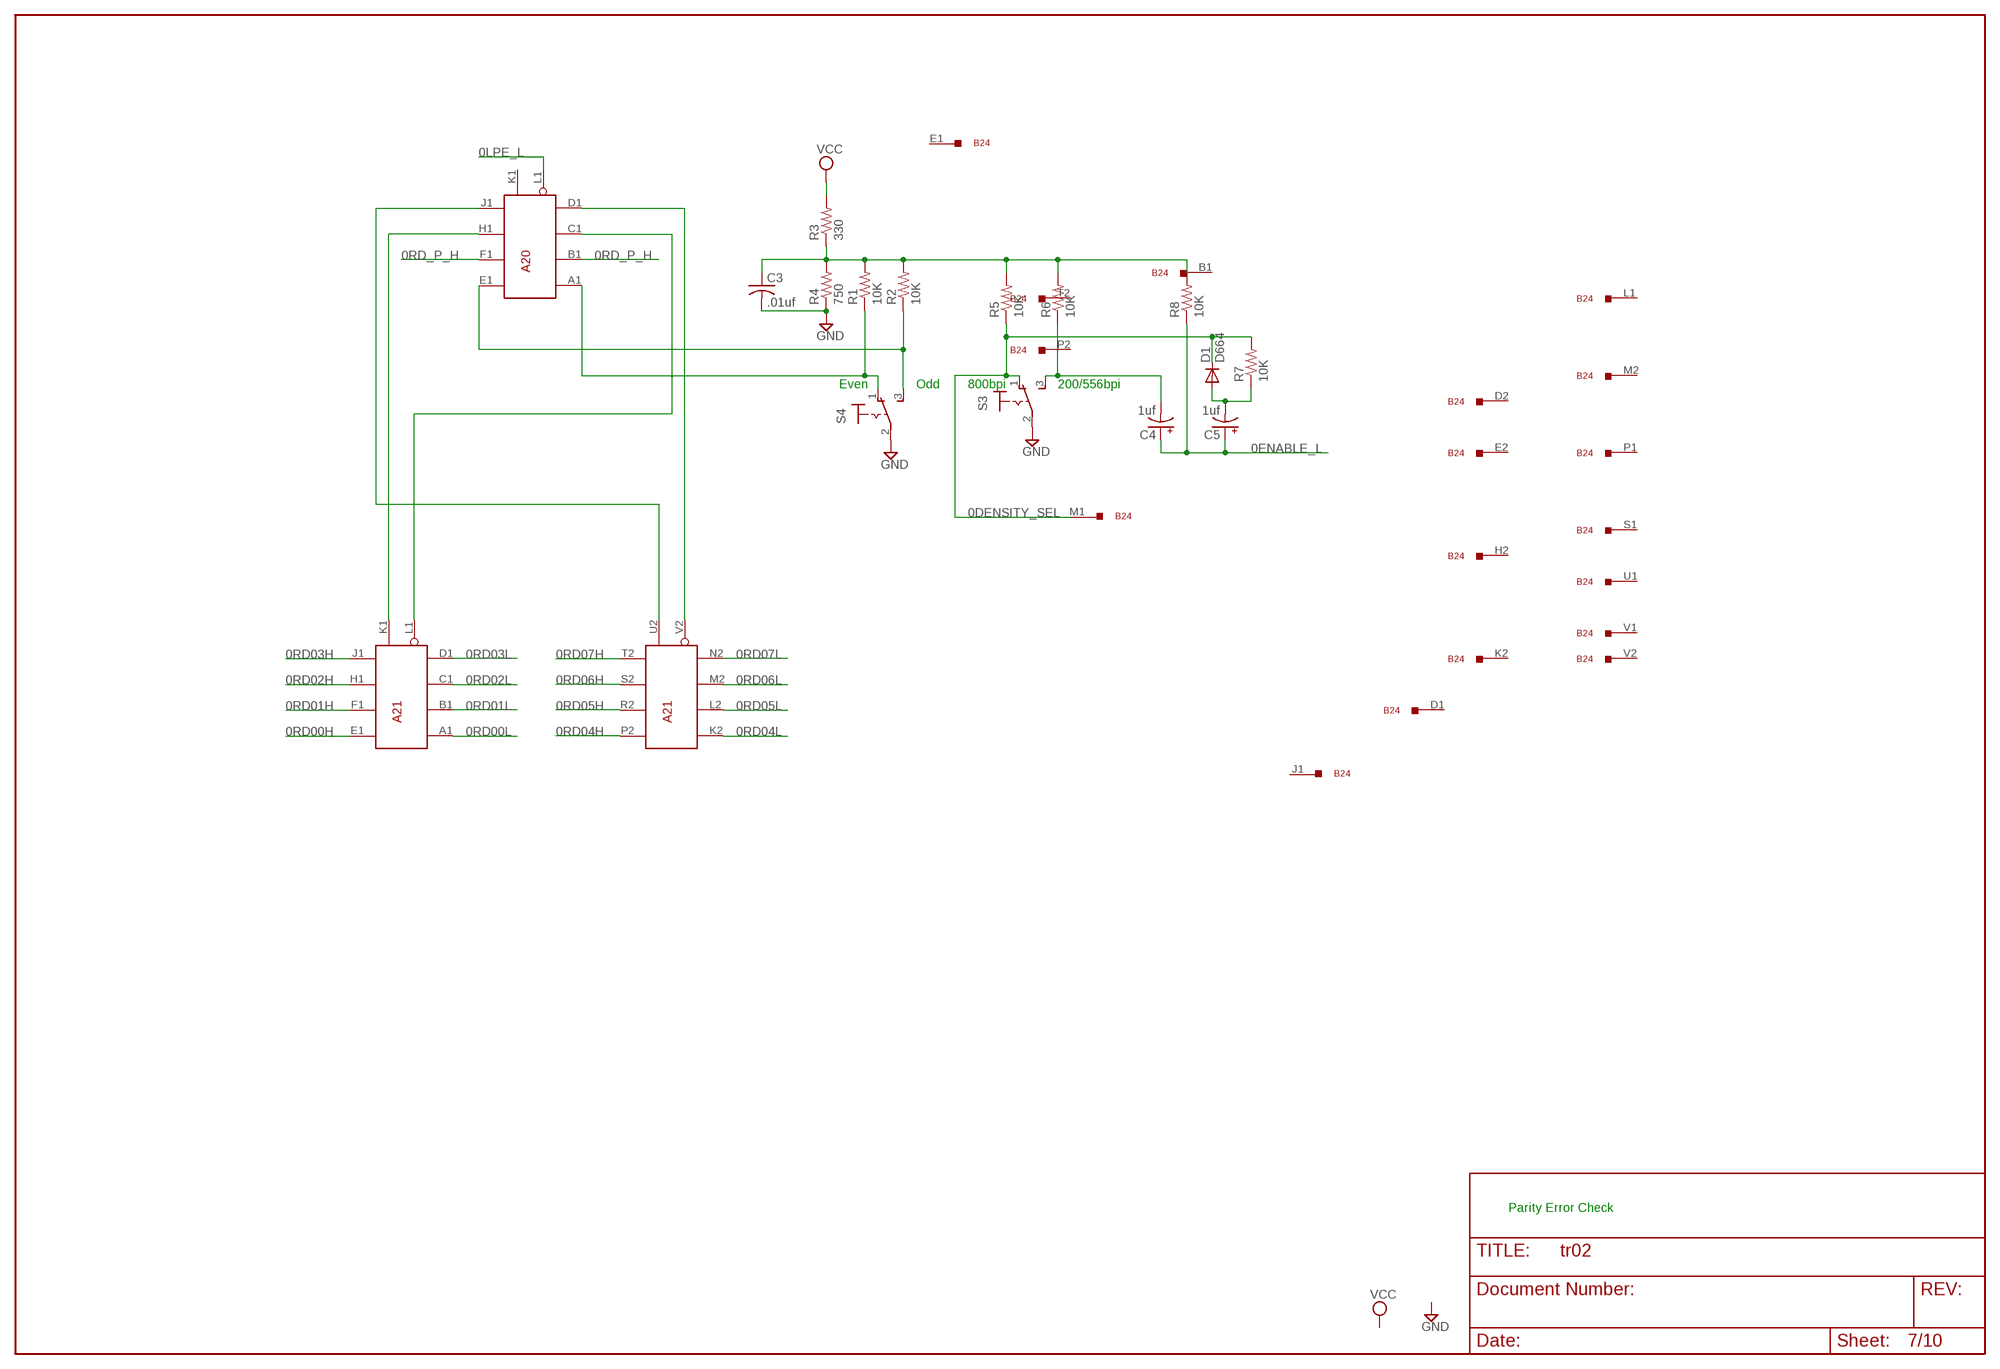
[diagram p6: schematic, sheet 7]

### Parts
A20  M162  [H807]
A21  M162  [H807]
C3  .01uf  C-US050-025X075  [C050-025X075]
C4  1uf  CPOL-USE22-6AXIAL  [E22-6]
C5  1uf  CPOL-USE22-6AXIAL  [E22-6]
D1  D664  1N4148  [DO35-10]
R1  10K  R-US_0207/10  [0207/10]
R2  10K  R-US_0207/10  [0207/10]
R3  330  R-US_0207/10  [0207/10]
R4  750  R-US_0207/10  [0207/10]
R5  10K  R-US_0207/10  [0207/10]
R6  10K  R-US_0207/10  [0207/10]
R7  10K  R-US_0207/10  [0207/10]
R8  10K  R-US_0207/10  [0207/10]
S3  320-916  [320-916]
S4  320-916  [320-916]

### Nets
0DENSITY_SEL: B24.M1 D1.C R5.1 R7.2 S3.1(O)
0ENABLE_L: C4.+ C5.+ R8.1 ; also sheet 3
0LPE_L: A20.L1(EVEN) ; also sheet 5
0RD00H: A21.E1(1A) ; also sheet 5
0RD00L: A21.A1(1B) ; also sheet 5
0RD01H: A21.F1(2A) ; also sheet 5
0RD01L: A21.B1(2B) ; also sheet 5
0RD02H: A21.H1(4A) ; also sheet 5
0RD02L: A21.C1(4B) ; also sheet 5
0RD03H: A21.J1(8A) ; also sheet 5
0RD03L: A21.D1(8B) ; also sheet 5
0RD04H: A21.P2(1A) ; also sheet 5
0RD04L: A21.K2(1B) ; also sheet 5
0RD05H: A21.R2(2A) ; also sheet 5
0RD05L: A21.L2(2B) ; also sheet 5
0RD06H: A21.S2(4A) ; also sheet 5
0RD06L: A21.M2(4B) ; also sheet 5
0RD07H: A21.T2(8A) ; also sheet 5
0RD07L: A21.N2(8B) ; also sheet 5
0RD_P_H: A20.B1(2B) A20.F1(2A) ; also sheet 5
GND [supply]: C3.2 R4.1 S3.2(P) S4.2(P) ; also sheet 3,5,6,10
N$61: A20.E1(1A) R2.1 S4.3(S)
N$64: A20.A1(1B) R1.1 S4.1(O)
N$66: A20.C1(4B) A21.L1(EVEN)
N$67: A20.J1(8A) A21.U2(ODD)
N$68: C5.- D1.A R7.1
N$69: A20.H1(4A) A21.K1(ODD)
N$70: A20.D1(8B) A21.V2(EVEN)
N$71: C3.1 R1.2 R2.2 R3.1 R4.2 R5.2 R6.2 R8.2
N$72: C4.- R6.1 S3.3(S)
VCC [supply]: R3.2
Unconnected: A20.K1(ODD) A20.K2(1B) A20.L2(2B) A20.M2(4B) A20.N2(8B) A20.P2(1A) A20.R2(2A) A20.S2(4A) A20.T2(8A) A20.U2(ODD) A20.V2(EVEN)

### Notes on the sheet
- Even | Odd | 800bpi | 200/556bpi
- Parity Error Check

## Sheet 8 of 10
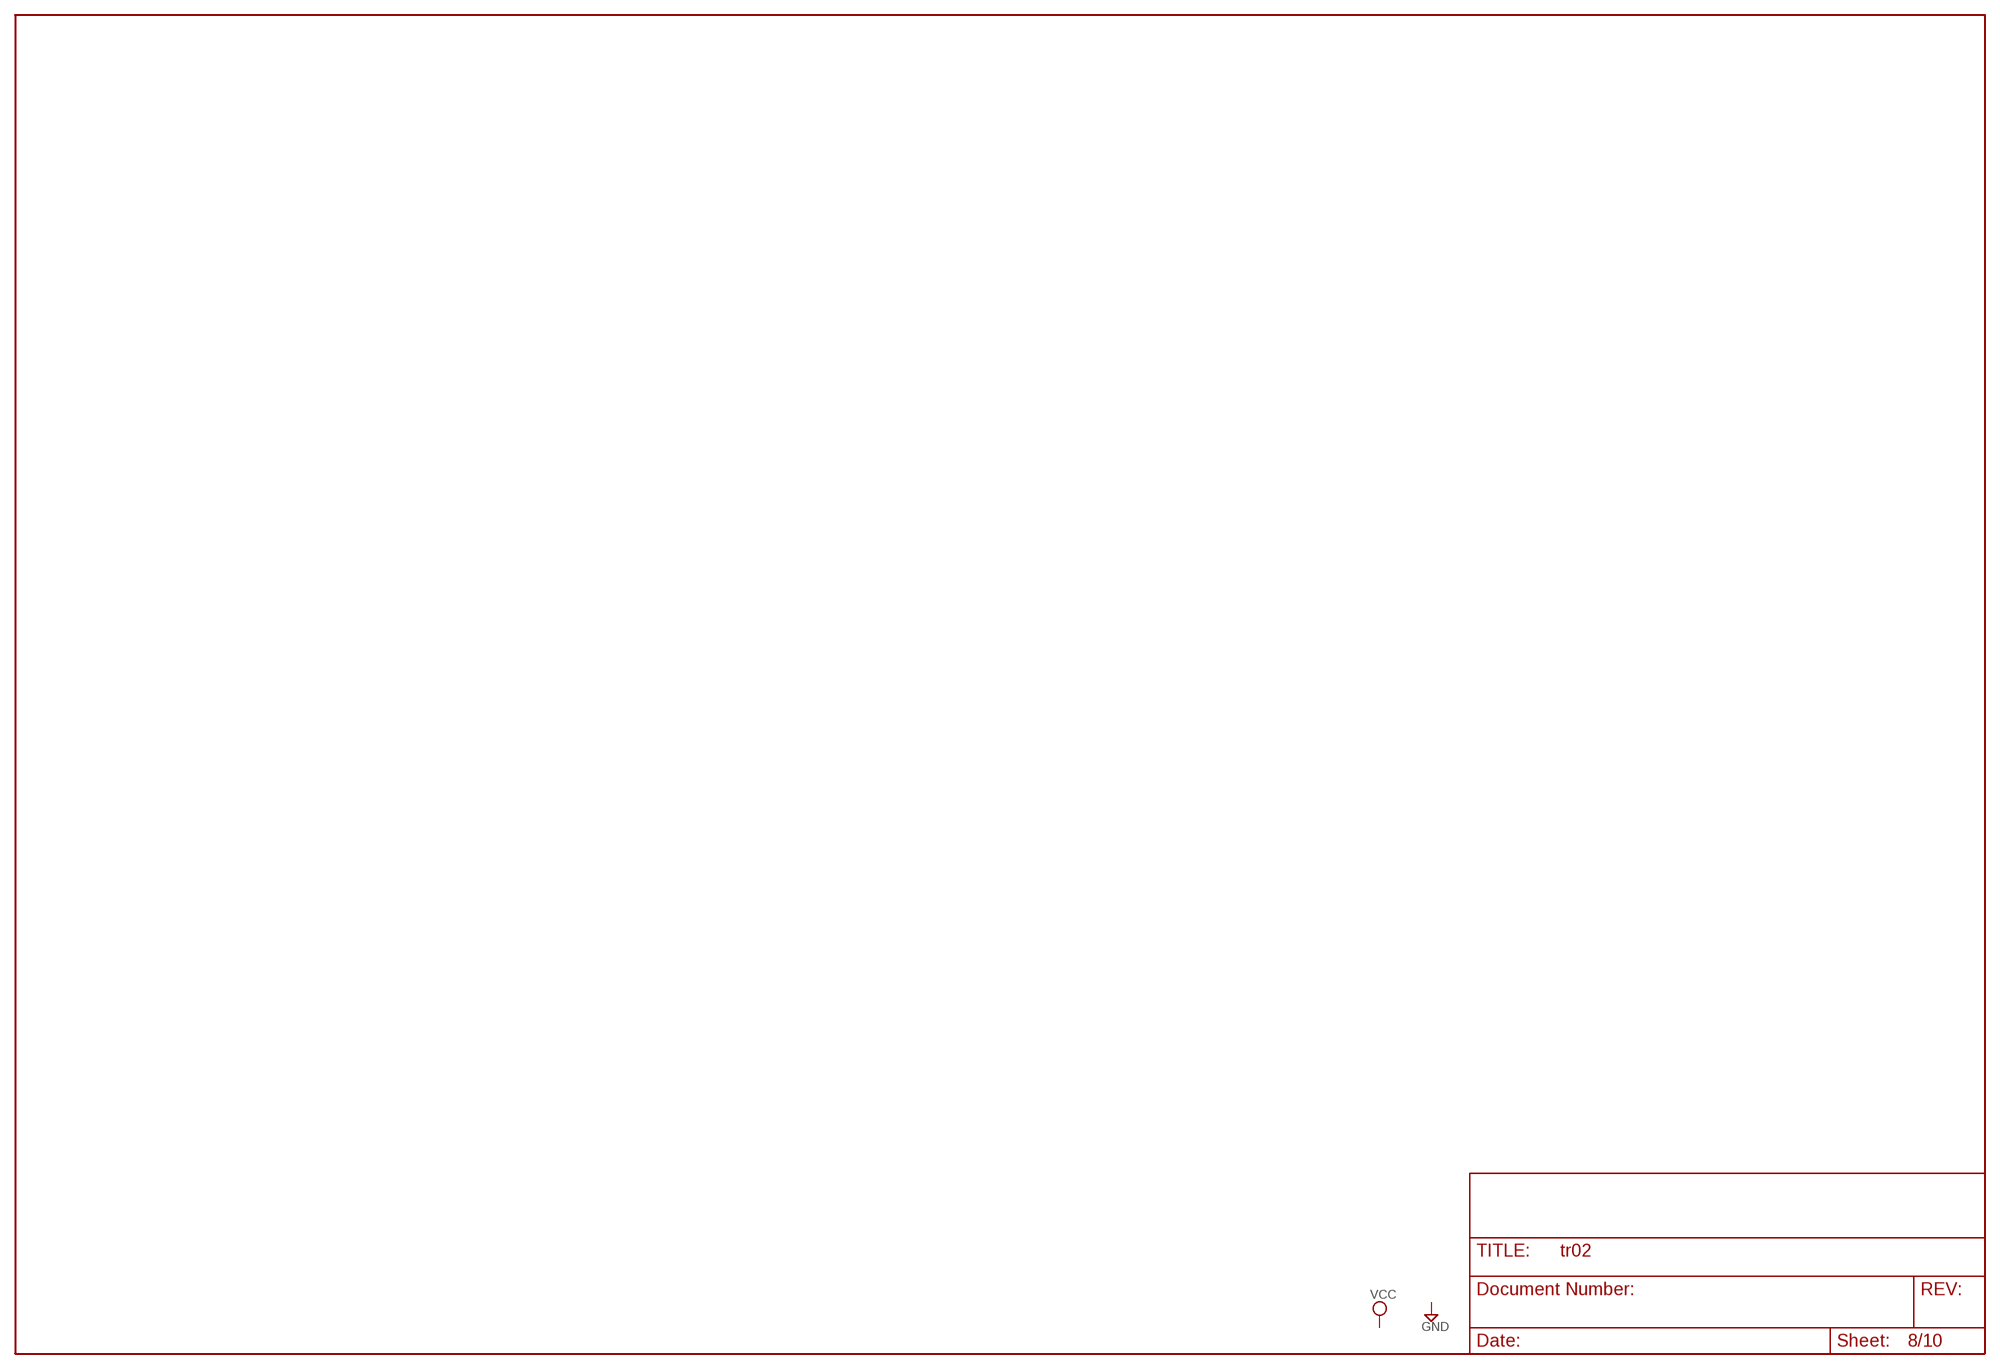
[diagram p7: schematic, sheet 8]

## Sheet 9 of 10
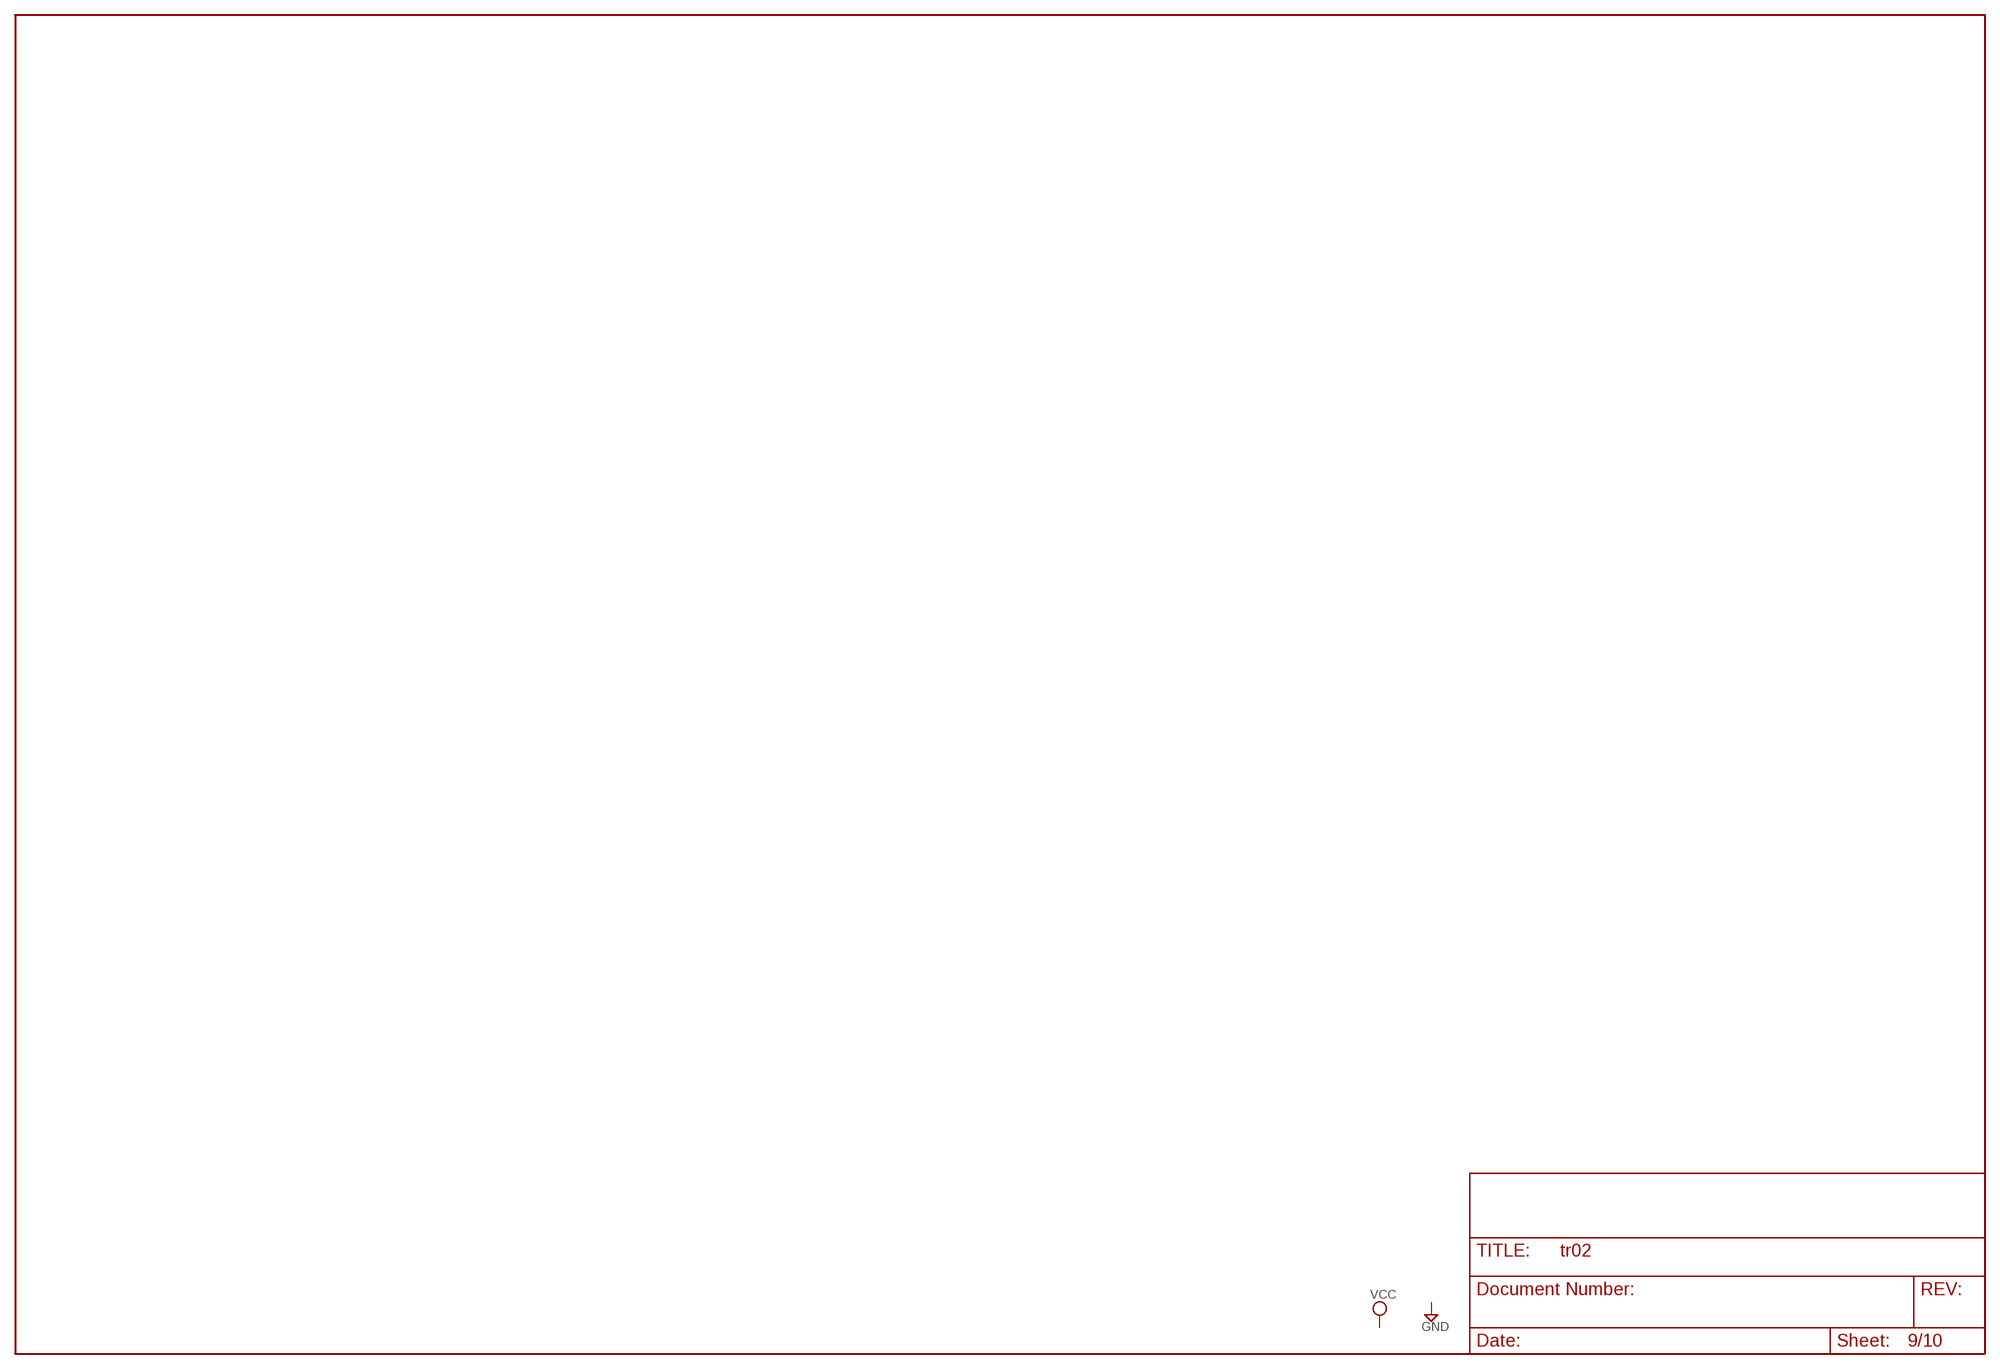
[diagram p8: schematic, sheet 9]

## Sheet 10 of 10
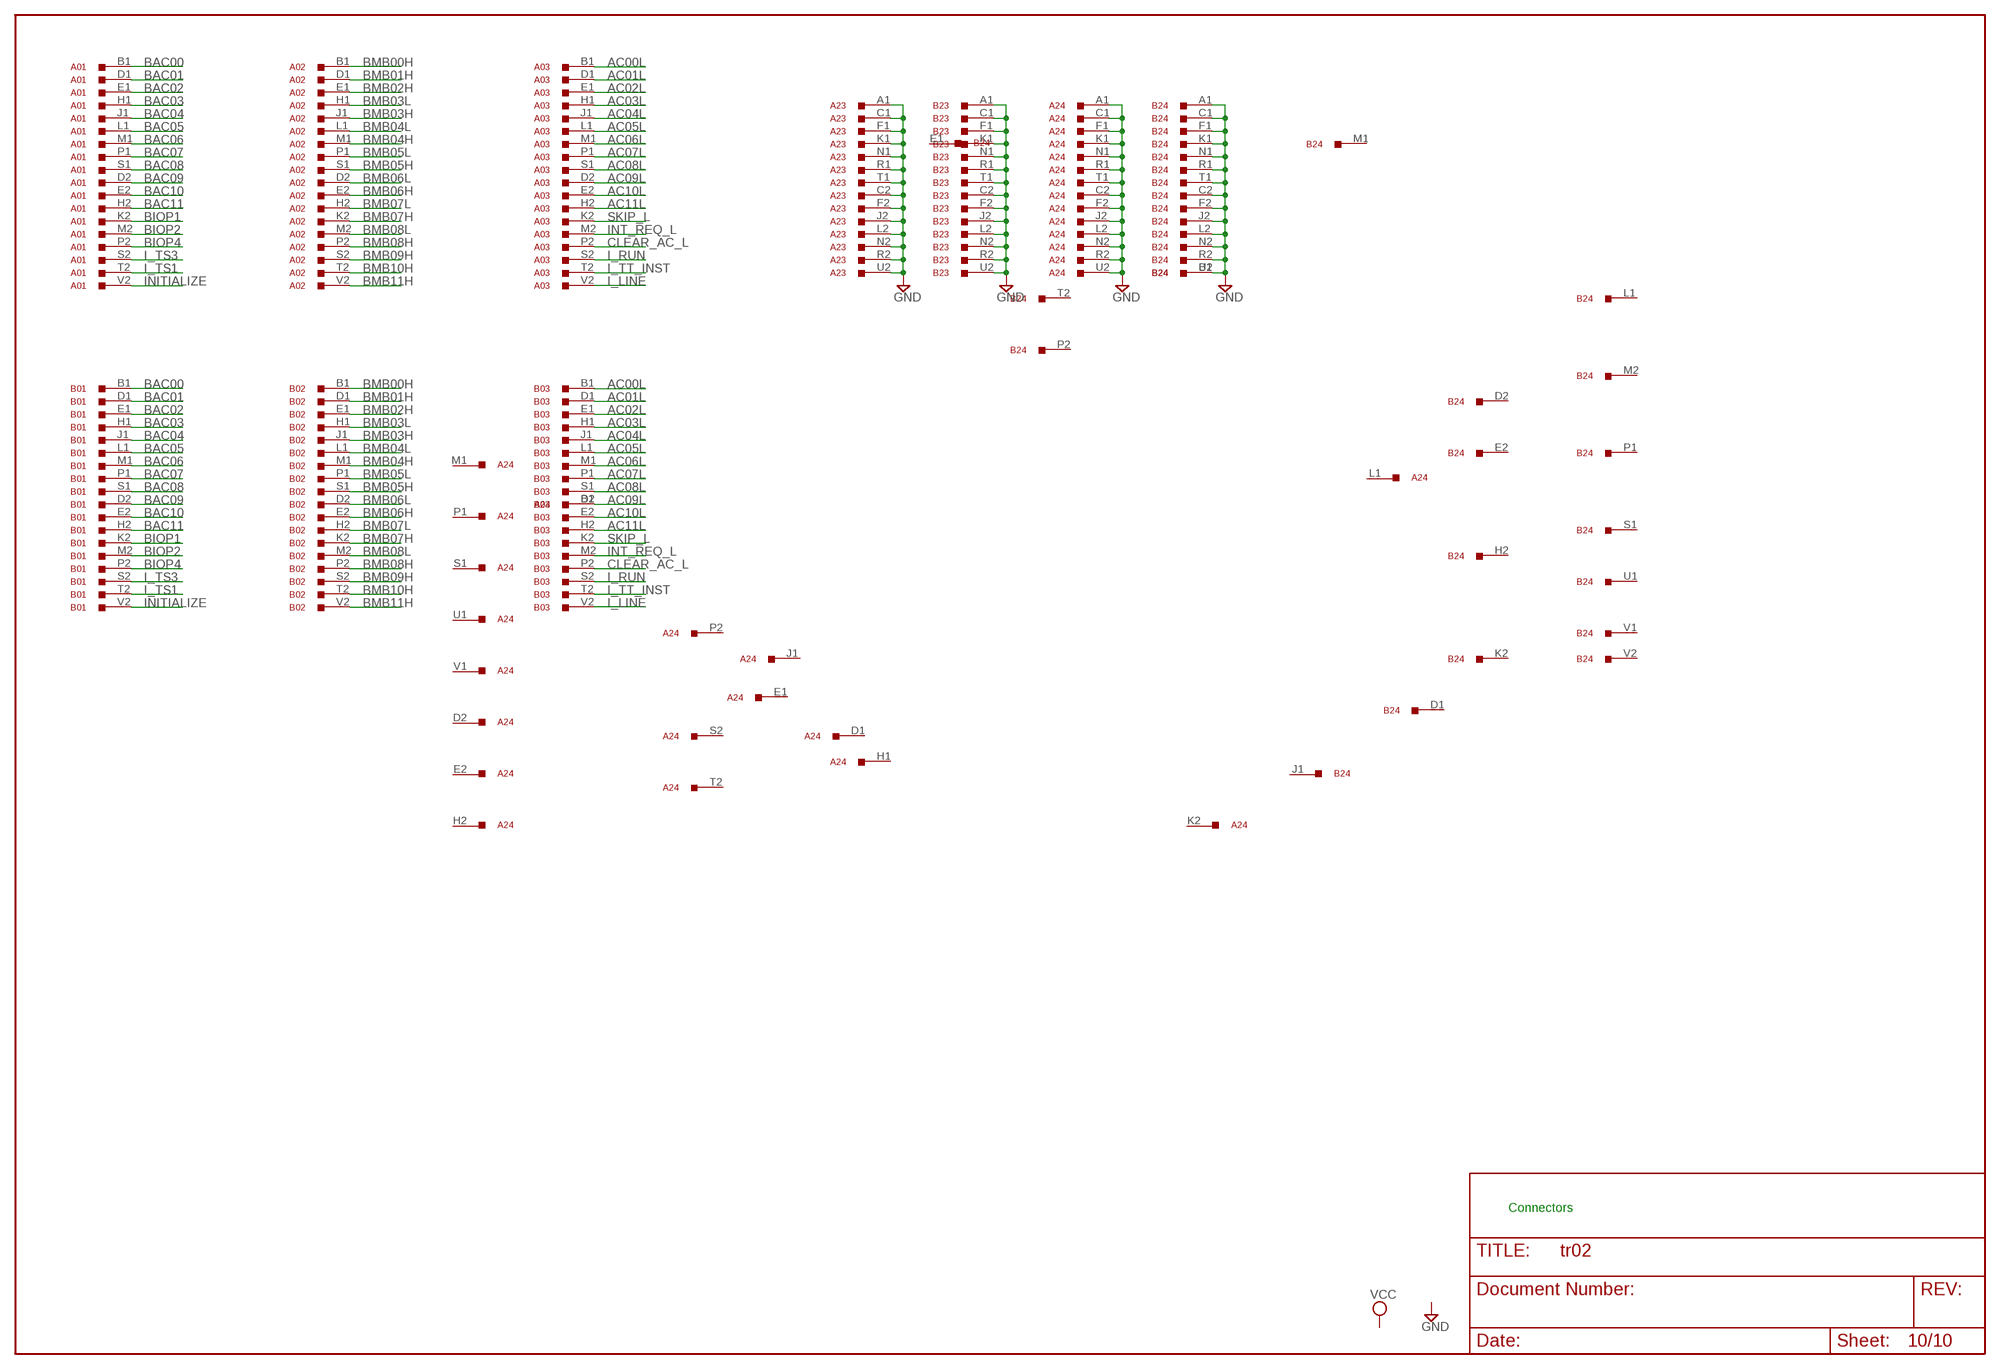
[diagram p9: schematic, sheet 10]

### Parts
A01  M903  [H807]
A02  M903  [H807]
A03  M903  [H807]
B01  M903  [H807]
B02  M903  [H807]
B03  M903  [H807]
B23  G784  M916  [H807]

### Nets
AC00L: A03.B1 B03.B1 ; also sheet 5
AC01L: A03.D1 B03.D1 ; also sheet 5
AC02L: A03.E1 B03.E1 ; also sheet 5
AC03L: A03.H1 B03.H1 ; also sheet 5
AC04L: A03.J1 B03.J1 ; also sheet 5
AC05L: A03.L1 B03.L1 ; also sheet 5
AC06L: A03.M1 B03.M1 ; also sheet 5
AC07L: A03.P1 B03.P1 ; also sheet 5
AC08L: A03.S1 B03.S1 ; also sheet 5
AC09L: A03.D2 B03.D2 ; also sheet 5
AC10L: A03.E2 B03.E2 ; also sheet 5
AC11L: A03.H2 B03.H2 ; also sheet 5
BAC00: A01.B1 B01.B1 ; also sheet 1,2
BAC01: A01.D1 B01.D1 ; also sheet 1,2
BAC02: A01.E1 B01.E1 ; also sheet 1,2
BAC03: A01.H1 B01.H1
BAC04: A01.J1 B01.J1 ; also sheet 1,2
BAC05: A01.L1 B01.L1 ; also sheet 1,2
BAC06: A01.M1 B01.M1 ; also sheet 1,2
BAC07: A01.P1 B01.P1 ; also sheet 1,2
BAC08: A01.S1 B01.S1 ; also sheet 1,2
BAC09: A01.D2 B01.D2 ; also sheet 1,2
BAC10: A01.E2 B01.E2 ; also sheet 1,2
BAC11: A01.H2 B01.H2 ; also sheet 1,2
BIOP1: A01.K2 B01.K2 ; also sheet 1,2
BIOP2: A01.M2 B01.M2 ; also sheet 1,2
BIOP4: A01.P2 B01.P2 ; also sheet 1,2
BMB00H: A02.B1 B02.B1
BMB01H: A02.D1 B02.D1
BMB02H: A02.E1 B02.E1
BMB03H: A02.J1 B02.J1 ; also sheet 1,2
BMB03L: A02.H1 B02.H1
BMB04H: A02.M1 B02.M1 ; also sheet 1,2
BMB04L: A02.L1 B02.L1
BMB05H: A02.S1 B02.S1 ; also sheet 1,2
BMB05L: A02.P1 B02.P1
BMB06H: A02.E2 B02.E2
BMB06L: A02.D2 B02.D2 ; also sheet 1,2
BMB07H: A02.K2 B02.K2
BMB07L: A02.H2 B02.H2 ; also sheet 1,2
BMB08H: A02.P2 B02.P2 ; also sheet 2
BMB08L: A02.M2 B02.M2 ; also sheet 1
BMB09H: A02.S2 B02.S2 ; also sheet 1,2
BMB10H: A02.T2 B02.T2 ; also sheet 1,2
BMB11H: A02.V2 B02.V2 ; also sheet 1,2
CLEAR_AC_L: A03.P2 B03.P2 ; also sheet 6
GND [supply]: A23.A1 A23.C1 A23.C2 A23.F1 A23.F2 A23.J2 A23.K1 A23.L2 A23.N1 A23.N2 A23.R1 A23.R2 A23.T1 A23.U2 A24.A1 A24.C1 A24.C2 A24.F1 A24.F2 A24.J2 A24.K1 A24.L2 A24.N1 A24.N2 A24.R1 A24.R2 A24.T1 A24.U2 B23.A1 B23.C1 B23.C2 B23.F1 B23.F2 B23.J2 B23.K1 B23.L2 B23.N1 B23.N2 B23.R1 B23.R2 B23.T1 B23.U2 B24.A1 B24.C1 B24.C2 B24.F1 B24.F2 B24.J2 B24.K1 B24.L2 B24.N1 B24.N2 B24.R1 B24.R2 B24.T1 B24.U2 ; also sheet 3,5,6,7
I_LINE: A03.V2 B03.V2
I_RUN: A03.S2 B03.S2
I_TS1: A01.T2 B01.T2
I_TS3: A01.S2 B01.S2
I_TT_INST: A03.T2 B03.T2
INITIALIZE: A01.V2 B01.V2 ; also sheet 1,2
INT_REQ_L: A03.M2 B03.M2 ; also sheet 6
SKIP_L: A03.K2 B03.K2 ; also sheet 6
Unconnected: B23.A2 B23.B1 B23.B2 B23.D1 B23.D2 B23.E1 B23.E2 B23.H1 B23.H2 B23.J1 B23.K2 B23.L1 B23.M1 B23.M2 B23.P1 B23.P2 B23.S1 B23.S2 B23.T2 B23.U1 B23.V1 B23.V2

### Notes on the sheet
- Connectors

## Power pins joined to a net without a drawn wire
GND: A01.A1 A01.C1 A01.C2 A01.F1 A01.F2 A01.J2 A01.K1 A01.L2 A01.N1 A01.N2 A01.R1 A01.R2 A01.T1 A01.U2 A02.A1 A02.C1 A02.C2 A02.F1 A02.F2 A02.J2 A02.K1 A02.L2 A02.N1 A02.N2 A02.R1 A02.R2 A02.T1 A02.U2 A03.A1 A03.C1 A03.C2 A03.F1 A03.F2 A03.J2 A03.K1 A03.L2 A03.N1 A03.N2 A03.R1 A03.R2 A03.T1 A03.U2 A04.C2(GND) A04.T1(GND) A04.U1(GND) A04.V1(GND) A05.C2(GND) A05.T1(GND) A05.U1(GND) A05.V1(GND) A06.C2(GND) A06.T1(GND) A07.C2(GND) A07.T1(GND) A08.C2(GND) A08.T1(GND) A09.C2(GND) A09.T1(GND) A10.C2(GND) A10.T1(GND) A11.C2(GND) A11.T1(GND) A12.C2(GND) A12.T1(GND) A13.C2(GND) A13.T1(GND) A14.C2(GND) A14.T1(GND) A15.C2(GND) A15.T1(GND) A16.C2(GND) A16.T1(GND) A17.C2(GND) A17.T1(GND) A18.C2(GND) A18.T1(GND) A19.C2(GND) A19.T1(GND) A20.C2(GND) A20.T1(GND) A21.C2(GND) A21.T1(GND) A22.C2(GND) A22.T1(GND) B01.A1 B01.C1 B01.C2 B01.F1 B01.F2 B01.J2 B01.K1 B01.L2 B01.N1 B01.N2 B01.R1 B01.R2 B01.T1 B01.U2 B02.A1 B02.C1 B02.C2 B02.F1 B02.F2 B02.J2 B02.K1 B02.L2 B02.N1 B02.N2 B02.R1 B02.R2 B02.T1 B02.U2 B03.A1 B03.C1 B03.C2 B03.F1 B03.F2 B03.J2 B03.K1 B03.L2 B03.N1 B03.N2 B03.R1 B03.R2 B03.T1 B03.U2 B06.C2(GND) B06.T1(GND) B07.C2(GND) B07.T1(GND) B08.C2(GND) B08.T1(GND) B09.C2(GND) B09.T1(GND) B11.C2(GND) B11.T1(GND) B15.C2(GND) B15.T1(GND) B18.C2(GND) B18.T1(GND)
VCC: A04.A2(VCC) A05.A2(VCC) A06.A2(VCC) A07.A2(VCC) A08.A2(VCC) A09.A2(VCC) A10.A2(VCC) A11.A2(VCC) A12.A2(VCC) A13.A2(VCC) A14.A2(VCC) A15.A2(VCC) A16.A2(VCC) A17.A2(VCC) A18.A2(VCC) A19.A2(VCC) A20.A2(VCC) A21.A2(VCC) A22.A2(VCC) B06.A2(VCC) B07.A2(VCC) B08.A2(VCC) B09.A2(VCC) B11.A2(VCC) B15.A2(VCC) B18.A2(VCC)

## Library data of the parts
A01-A03 B01-B03 = dec-m:M903: Two-sided Posibus cable/connector.
A04 A05 = dec-m:M623: 6 Dual Bus Drivers
A06 B06 = dec-m:M103: M103 Device Selector Used to decode IOT requests.
A07 B07 = dec-m:M101: Bus Data Interface The M101 contains 15 two-input NAND gates. One input of each gate is tied to a common line so that all data signals can be enabled simultaneously. Each data signal presents one TTL load. The common input presents 15 loads. Each output can drive 10 loads. Power: 5V@82ma (max.)
A08 A16 A22 B08 = dec-m:M111: Sixteen inverters.
A09 A15 B09 B15 = dec-m:M115: 8 3-input NAND Gates
A10 A14 = dec-m:M206X: Two sets of 3 D flip-flops
A11 A17 B11 = dec-m:M113: 10 2-input NAND Gates
A12 A18 B18 = dec-m:M117: 6 4-input NAND Gates
A13 = dec-m:M307: Dual Integrating One-Shot
A19 = dec-m:M302: Dual one-shot
A20 A21 = dec-m:M162: Parity Circuit
A23 A24 B23 B24 = dec-m:M916: Simple 36 pin connector/wire cable
C1 C2 C4 C5 = rcl:CPOL-US: POLARIZED CAPACITOR, American symbol
C3 = rcl:C-US: CAPACITOR, American symbol
D1 = diode:1N4148: DIODE
R1-R8 = rcl:R-US_: RESISTOR, American symbol
S3 S4 = switch:320-916: TOGGLE SWITCH distributor RS Components

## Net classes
1 supply: width 0.203 mm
